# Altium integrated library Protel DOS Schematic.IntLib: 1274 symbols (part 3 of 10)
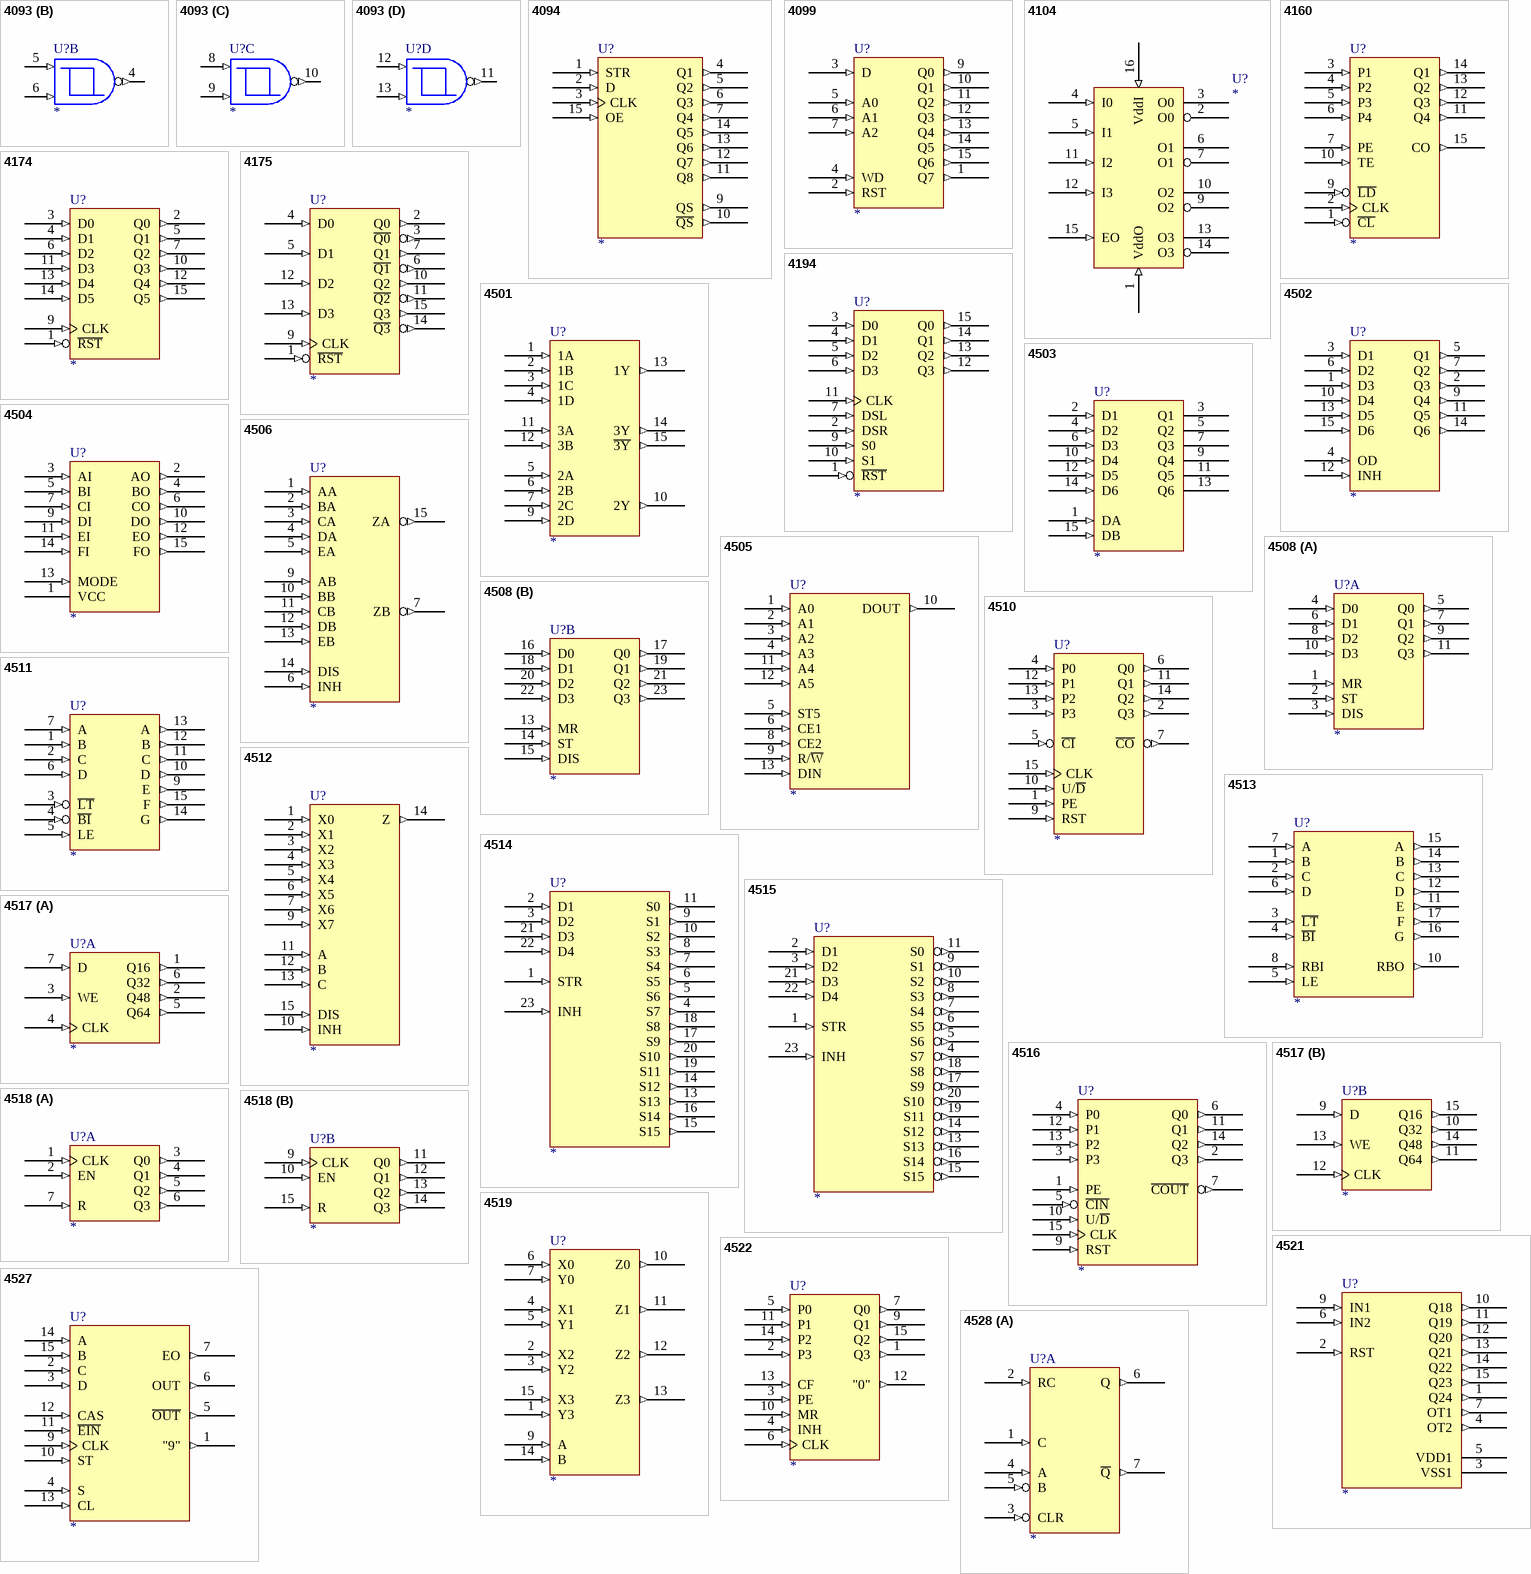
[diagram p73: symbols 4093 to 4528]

## 4511
designator U?
footprint DIP16E
footprint DIP-16
pins: 1 B (in), 2 C (in), 3 ~{LT} (in), 4 ~{BI} (in), 5 LE (in), 6 D (in), 7 A (in), 8 GND (power) hidden to GND, 9 E (out), 10 D (out), 11 C (out), 12 B (out), 13 A (out), 14 G (out), 15 F (out), 16 VCC (power) hidden to VCC
2 alternate drawings of the same symbol

## 4512
designator U?
footprint DIP-16
pins: 1 X0 (in), 2 X1 (in), 3 X2 (in), 4 X3 (in), 5 X4 (in), 6 X5 (in), 7 X6 (in), 8 GND (power) hidden to GND, 9 X7 (in), 10 INH (in), 11 A (in), 12 B (in), 13 C (in), 14 Z (out), 15 DIS (in), 16 VCC (power) hidden to VCC
2 alternate drawings of the same symbol

## 4513
designator U?
footprint DIP-18
pins: 1 B (in), 2 C (in), 3 ~{LT} (in), 4 ~{BI} (in), 5 LE (in), 6 D (in), 7 A (in), 8 RBI (in), 9 GND (power) hidden to GND, 10 RBO (out), 11 E (out), 12 D (out), 13 C (out), 14 B (out), 15 A (out), 16 G (out), 17 F (out), 18 VCC (power) hidden to VCC
2 alternate drawings of the same symbol

## 4514
designator U?
footprint DIP-24
pins: 1 STR (in), 2 D1 (in), 3 D2 (in), 4 S7 (out), 5 S6 (out), 6 S5 (out), 7 S4 (out), 8 S3 (out), 9 S1 (out), 10 S2 (out), 11 S0 (out), 12 GND (power) hidden to GND, 13 S13 (out), 14 S12 (out), 15 S15 (out), 16 S14 (out), 17 S9 (out), 18 S8 (out), 19 S11 (out), 20 S10 (out), 21 D3 (in), 22 D4 (in), 23 INH (in), 24 VCC (power) hidden to VCC
2 alternate drawings of the same symbol

## 4515
designator U?
footprint DIP-24
pins: 1 STR (in), 2 D1 (in), 3 D2 (in), 4 S7 (out), 5 S6 (out), 6 S5 (out), 7 S4 (out), 8 S3 (out), 9 S1 (out), 10 S2 (out), 11 S0 (out), 12 GND (power) hidden to GND, 13 S13 (out), 14 S12 (out), 15 S15 (out), 16 S14 (out), 17 S9 (out), 18 S8 (out), 19 S11 (out), 20 S10 (out), 21 D3 (in), 22 D4 (in), 23 INH (in), 24 VCC (power) hidden to VCC
2 alternate drawings of the same symbol

## 4516
designator U?
footprint DIP16E
pins: 1 PE (in), 2 Q3 (out), 3 P3 (in), 4 P0 (in), 5 ~{CIN} (in), 6 Q0 (out), 7 ~{COUT} (out), 8 GND (power) hidden to GND, 9 RST (in), 10 U/~{D} (in), 11 Q1 (out), 12 P1 (in), 13 P2 (in), 14 Q2 (out), 15 CLK (in), 16 VCC (power) hidden to VCC
2 alternate drawings of the same symbol

## 4517
designator U?
footprint DIP-16
part A pins: 1 Q16 (out), 2 Q48 (out), 3 WE (in), 4 CLK (in), 5 Q64 (out), 6 Q32 (out), 7 D (in), 8 GND (power) hidden to GND, 16 VCC (power) hidden to VCC
part B pins: 8 GND (power) hidden to GND, 9 D (in), 10 Q32 (out), 11 Q64 (out), 12 CLK (in), 13 WE (in), 14 Q48 (out), 15 Q16 (out), 16 VCC (power) hidden to VCC
2 alternate drawings of the same symbol

## 4518
designator U?
footprint DIP-16
part A pins: 1 CLK (in), 2 EN (in), 3 Q0 (out), 4 Q1 (out), 5 Q2 (out), 6 Q3 (out), 7 R (in), 8 GND (power) hidden to GND, 16 VCC (power) hidden to VCC
part B pins: 8 GND (power) hidden to GND, 9 CLK (in), 10 EN (in), 11 Q0 (out), 12 Q1 (out), 13 Q2 (out), 14 Q3 (out), 15 R (in), 16 VCC (power) hidden to VCC
2 alternate drawings of the same symbol

## 4519
designator U?
footprint DIP-16
pins: 1 Y3 (in), 2 X2 (in), 3 Y2 (in), 4 X1 (in), 5 Y1 (in), 6 X0 (in), 7 Y0 (in), 8 GND (power) hidden to GND, 9 A (in), 10 Z0 (out), 11 Z1 (out), 12 Z2 (out), 13 Z3 (out), 14 B (in), 15 X3 (in), 16 VCC (power) hidden to VCC
2 alternate drawings of the same symbol

## 4521
designator U?
footprint DIP-16
pins: 1 Q24 (out), 2 RST (in), 3 VSS1 (power), 4 OT2 (out), 5 VDD1 (power), 6 IN2 (in), 7 OT1 (out), 8 GND (power) hidden to GND, 9 IN1 (in), 10 Q18 (out), 11 Q19 (out), 12 Q20 (out), 13 Q21 (out), 14 Q22 (out), 15 Q23 (out), 16 VCC (power) hidden to VCC
2 alternate drawings of the same symbol

## 4522
designator U?
footprint DIP-16
pins: 1 Q3 (out), 2 P3 (in), 3 PE (in), 4 INH (in), 5 P0 (in), 6 CLK (in), 7 Q0 (out), 8 GND (power) hidden to GND, 9 Q1 (out), 10 MR (in), 11 P1 (in), 12 "0" (out), 13 CF (in), 14 P2 (in), 15 Q2 (out), 16 VCC (power) hidden to VCC
2 alternate drawings of the same symbol

## 4527
designator U?
footprint DIP-16
pins: 1 "9" (out), 2 C (in), 3 D (in), 4 S (in), 5 ~{OUT} (out), 6 OUT (out), 7 EO (out), 8 GND (power) hidden to GND, 9 CLK (in), 10 ST (in), 11 ~{EIN} (in), 12 CAS (in), 13 CL (in), 14 A (in), 15 B (in), 16 VCC (power) hidden to VCC
2 alternate drawings of the same symbol

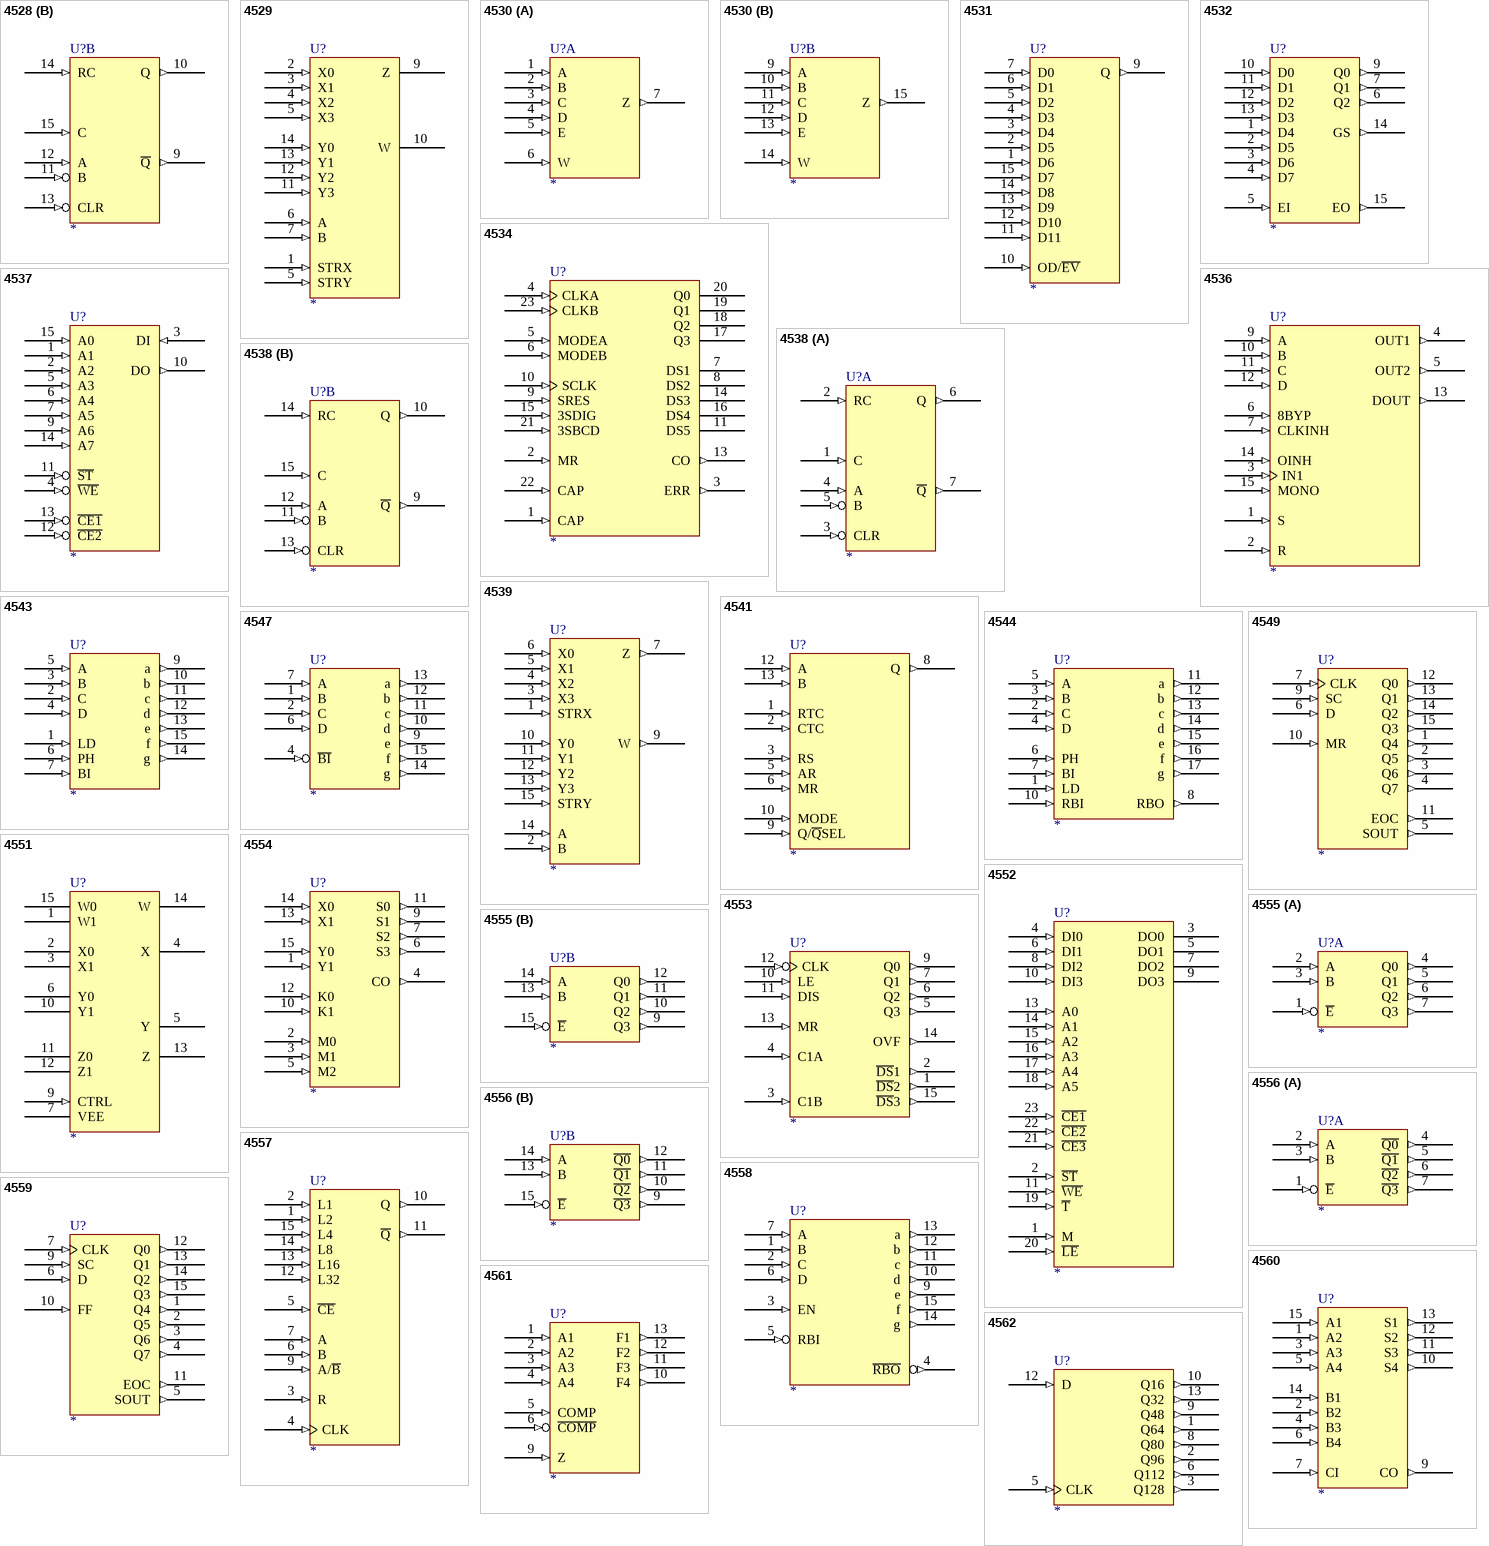
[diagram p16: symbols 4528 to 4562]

## 4528
designator U?
footprint DIP-16
part A pins: 1 C (in), 2 RC (in), 3 CLR (in), 4 A (in), 5 B (in), 6 Q (out), 7 ~{Q} (out), 8 GND (power) hidden to GND, 16 VCC (power) hidden to VCC
part B pins: 8 GND (power) hidden to GND, 9 ~{Q} (out), 10 Q (out), 11 B (in), 12 A (in), 13 CLR (in), 14 RC (in), 15 C (in), 16 VCC (power) hidden to VCC
2 alternate drawings of the same symbol

## 4529
designator U?
footprint DIP-16
pins: 1 STRX (in), 2 X0 (in), 3 X1 (in), 4 X2 (in), 5 X3 (in), 5 STRY (in), 6 A (in), 7 B (in), 8 GND (power) hidden to GND, 9 Z, 10 W, 11 Y3 (in), 12 Y2 (in), 13 Y1 (in), 14 Y0 (in), 16 VCC (power) hidden to VCC
2 alternate drawings of the same symbol

## 4530
designator U?
footprint DIP-16
part A pins: 1 A (in), 2 B (in), 3 C (in), 4 D (in), 5 E (in), 6 W (in), 7 Z (out), 8 GND (power) hidden to GND, 16 VCC (power) hidden to VCC
part B pins: 8 GND (power) hidden to GND, 9 A (in), 10 B (in), 11 C (in), 12 D (in), 13 E (in), 14 W (in), 15 Z (out), 16 VCC (power) hidden to VCC
2 alternate drawings of the same symbol

## 4531
designator U?
footprint DIP-16
pins: 1 D6 (in), 2 D5 (in), 3 D4 (in), 4 D3 (in), 5 D2 (in), 6 D1 (in), 7 D0 (in), 8 GND (power) hidden to GND, 9 Q (out), 10 OD/~{EV} (in), 11 D11 (in), 12 D10 (in), 13 D9 (in), 14 D8 (in), 15 D7 (in), 16 VCC (power) hidden to VCC
2 alternate drawings of the same symbol

## 4532
designator U?
footprint DIP-16
pins: 1 D4 (in), 2 D5 (in), 3 D6 (in), 4 D7 (in), 5 EI (in), 6 Q2 (out), 7 Q1 (out), 8 GND (power) hidden to GND, 9 Q0 (out), 10 D0 (in), 11 D1 (in), 12 D2 (in), 13 D3 (in), 14 GS (out), 15 EO (out), 16 VCC (power) hidden to VCC
2 alternate drawings of the same symbol

## 4534
designator U?
footprint DIP-24
pins: 1 CAP (in), 2 MR (in), 3 ERR (out), 4 CLKA (in), 5 MODEA (in), 6 MODEB (in), 7 DS1 (hiz), 8 DS2 (hiz), 9 SRES (in), 10 SCLK (in), 11 DS5 (hiz), 12 GND (power) hidden to GND, 13 CO (out), 14 DS3 (hiz), 15 3SDIG (in), 16 DS4 (hiz), 17 Q3 (hiz), 18 Q2 (hiz), 19 Q1 (hiz), 20 Q0 (hiz), 21 3SBCD (in), 22 CAP (in), 23 CLKB (in), 24 VCC (power) hidden to VCC
2 alternate drawings of the same symbol

## 4536
designator U?
footprint DIP-16
pins: 1 S (in), 2 R (in), 3 IN1 (in), 4 OUT1 (out), 5 OUT2 (out), 6 8BYP (in), 7 CLKINH (in), 8 GND (power) hidden to GND, 9 A (in), 10 B (in), 11 C (in), 12 D (in), 13 DOUT (out), 14 OINH (in), 15 MONO (in), 16 VCC (power) hidden to VCC
2 alternate drawings of the same symbol

## 4537
designator U?
footprint DIP-16
pins: 1 A1 (in), 2 A2 (in), 3 DI (in), 4 ~{WE} (in), 5 A3 (in), 6 A4 (in), 7 A5 (in), 8 GND (power) hidden to GND, 9 A6 (in), 10 DO (out), 11 ~{ST} (in), 12 ~{CE2} (in), 13 ~{CE1} (in), 14 A7 (in), 15 A0 (in), 16 VCC (power) hidden to VCC
2 alternate drawings of the same symbol

## 4538
designator U?
footprint DIP-16
part A pins: 1 C (in), 2 RC (in), 3 CLR (in), 4 A (in), 5 B (in), 6 Q (out), 7 ~{Q} (out), 8 GND (power) hidden to GND, 16 VCC (power) hidden to VCC
part B pins: 8 GND (power) hidden to GND, 9 ~{Q} (out), 10 Q (out), 11 B (in), 12 A (in), 13 CLR (in), 14 RC (in), 15 C (in), 16 VCC (power) hidden to VCC
2 alternate drawings of the same symbol

## 4539
designator U?
footprint DIP-16
pins: 1 STRX (in), 2 B (in), 3 X3 (in), 4 X2 (in), 5 X1 (in), 6 X0 (in), 7 Z (out), 8 GND (power) hidden to GND, 9 W (out), 10 Y0 (in), 11 Y1 (in), 12 Y2 (in), 13 Y3 (in), 14 A (in), 15 STRY (in), 16 VCC (power) hidden to VCC
2 alternate drawings of the same symbol

## 4541
designator U?
footprint DIP-14
pins: 1 RTC (in), 2 CTC (in), 3 RS (in), 5 AR (in), 6 MR (in), 7 GND (power) hidden to GND, 8 Q (out), 9 Q/~{Q}SEL (in), 10 MODE (in), 12 A (in), 13 B (in), 14 VCC (power) hidden to VCC
2 alternate drawings of the same symbol

## 4543
designator U?
footprint DIP-16
pins: 1 LD (in), 2 C (in), 3 B (in), 4 D (in), 5 A (in), 6 PH (in), 7 BI (in), 8 GND (power) hidden to GND, 9 a (out), 10 b (out), 11 c (out), 12 d (out), 13 e (out), 14 g (out), 15 f (out), 16 VCC (power) hidden to VCC
2 alternate drawings of the same symbol

## 4544
designator U?
footprint DIP-18
pins: 1 LD (in), 2 C (in), 3 B (in), 4 D (in), 5 A (in), 6 PH (in), 7 BI (in), 8 RBO (out), 9 GND (power) hidden to GND, 10 RBI (in), 11 a (out), 12 b (out), 13 c (out), 14 d (out), 15 e (out), 16 f (out), 17 g (out), 18 VCC (power) hidden to VCC
2 alternate drawings of the same symbol

## 4547
designator U?
footprint DIP-16
pins: 1 B (in), 2 C (in), 4 ~{BI} (in), 6 D (in), 7 A (in), 8 GND (power) hidden to GND, 9 e (out), 10 d (out), 11 c (out), 12 b (out), 13 a (out), 14 g (out), 15 f (out), 16 VCC (power) hidden to VCC
2 alternate drawings of the same symbol

## 4549
designator U?
footprint DIP-16
pins: 1 Q4 (out), 2 Q5 (out), 3 Q6 (out), 4 Q7 (out), 5 SOUT (out), 6 D (in), 7 CLK (in), 8 GND (power) hidden to GND, 9 SC (in), 10 MR (in), 11 EOC (out), 12 Q0 (out), 13 Q1 (out), 14 Q2 (out), 15 Q3 (out), 16 VCC (power) hidden to VCC
2 alternate drawings of the same symbol

## 4551
designator U?
footprint DIP-16
pins: 1 W1, 2 X0, 3 X1, 4 X, 5 Y, 6 Y0, 7 VEE, 8 GND (power) hidden to GND, 9 CTRL (in), 10 Y1, 11 Z0, 12 Z1, 13 Z, 14 W, 15 W0, 16 VCC (power) hidden to VCC
2 alternate drawings of the same symbol

## 4552
designator U?
footprint DIP-24
pins: 1 M (in), 2 ~{ST} (in), 3 DO0 (hiz), 4 DI0 (in), 5 DO1 (hiz), 6 DI1 (in), 7 DO2 (hiz), 8 DI2 (in), 9 DO3 (hiz), 10 DI3 (in), 11 ~{WE} (in), 12 GND (power) hidden to GND, 13 A0 (in), 14 A1 (in), 15 A2 (in), 16 A3 (in), 17 A4 (in), 18 A5 (in), 19 ~{T} (in), 20 ~{LE} (in), 21 ~{CE3} (in), 22 ~{CE2} (in), 23 ~{CE1} (in), 24 VCC (power) hidden to VCC
2 alternate drawings of the same symbol

## 4553
designator U?
footprint DIP16E
footprint DIP-16
pins: 1 ~{DS}2 (out), 2 ~{DS}1 (out), 3 C1B (in), 4 C1A (in), 5 Q3 (out), 6 Q2 (out), 7 Q1 (out), 8 GND (power) hidden to GND, 9 Q0 (out), 10 LE (in), 11 DIS (in), 12 CLK (in), 13 MR (in), 14 OVF (out), 15 ~{DS}3 (out), 16 VCC (power) hidden to VCC
2 alternate drawings of the same symbol

## 4554
designator U?
footprint DIP-16
pins: 1 Y1 (in), 2 M0 (in), 3 M1 (in), 4 CO (out), 5 M2 (in), 6 S3 (out), 7 S2 (out), 8 GND (power) hidden to GND, 9 S1 (out), 10 K1 (in), 11 S0 (out), 12 K0 (in), 13 X1 (in), 14 X0 (in), 15 Y0 (in), 16 VCC (power) hidden to VCC
2 alternate drawings of the same symbol

## 4555
designator U?
footprint DIP-16
part A pins: 1 ~{E} (in), 2 A (in), 3 B (in), 4 Q0 (out), 5 Q1 (out), 6 Q2 (out), 7 Q3 (out), 8 GND (power) hidden to GND, 16 VCC (power) hidden to VCC
part B pins: 8 GND (power) hidden to GND, 9 Q3 (out), 10 Q2 (out), 11 Q1 (out), 12 Q0 (out), 13 B (in), 14 A (in), 15 ~{E} (in), 16 VCC (power) hidden to VCC
2 alternate drawings of the same symbol

## 4556
designator U?
footprint DIP-16
part A pins: 1 ~{E} (in), 2 A (in), 3 B (in), 4 ~{Q0} (out), 5 ~{Q1} (out), 6 ~{Q2} (out), 7 ~{Q3} (out), 8 GND (power) hidden to GND, 16 VCC (power) hidden to VCC
part B pins: 8 GND (power) hidden to GND, 9 ~{Q3} (out), 10 ~{Q2} (out), 11 ~{Q1} (out), 12 ~{Q0} (out), 13 B (in), 14 A (in), 15 ~{E} (in), 16 VCC (power) hidden to VCC
2 alternate drawings of the same symbol

## 4557
designator U?
footprint DIP-16
pins: 1 L2 (in), 2 L1 (in), 3 R (in), 4 CLK (in), 5 ~{CE} (in), 6 B (in), 7 A (in), 8 GND (power) hidden to GND, 9 A/~{B} (in), 10 Q (out), 11 ~{Q} (out), 12 L32 (in), 13 L16 (in), 14 L8 (in), 15 L4 (in), 16 VCC (power) hidden to VCC
2 alternate drawings of the same symbol

## 4558
designator U?
footprint DIP-16
pins: 1 B (in), 2 C (in), 3 EN (in), 4 ~{RBO} (out), 5 RBI (in), 6 D (in), 7 A (in), 8 GND (power) hidden to GND, 9 e (out), 10 d (out), 11 c (out), 12 b (out), 13 a (out), 14 g (out), 15 f (out), 16 VCC (power) hidden to VCC
2 alternate drawings of the same symbol

## 4559
designator U?
footprint DIP-16
pins: 1 Q4 (out), 2 Q5 (out), 3 Q6 (out), 4 Q7 (out), 5 SOUT (out), 6 D (in), 7 CLK (in), 8 GND (power) hidden to GND, 9 SC (in), 10 FF (in), 11 EOC (out), 12 Q0 (out), 13 Q1 (out), 14 Q2 (out), 15 Q3 (out), 16 VCC (power) hidden to VCC
2 alternate drawings of the same symbol

## 4560
designator U?
footprint DIP-16
pins: 1 A2 (in), 2 B2 (in), 3 A3 (in), 4 B3 (in), 5 A4 (in), 6 B4 (in), 7 CI (in), 8 GND (power) hidden to GND, 9 CO (out), 10 S4 (out), 11 S3 (out), 12 S2 (out), 13 S1 (out), 14 B1 (in), 15 A1 (in), 16 VCC (power) hidden to VCC
2 alternate drawings of the same symbol

## 4561
designator U?
footprint DIP-14
pins: 1 A1 (in), 2 A2 (in), 3 A3 (in), 4 A4 (in), 5 COMP (in), 6 ~{COMP} (in), 7 GND (power) hidden to GND, 9 Z (in), 10 F4 (out), 11 F3 (out), 12 F2 (out), 13 F1 (out), 14 VCC (power) hidden to VCC
2 alternate drawings of the same symbol

## 4562
designator U?
footprint DIP-14
pins: 1 Q64 (out), 2 Q96 (out), 3 Q128 (out), 5 CLK (in), 6 Q112 (out), 7 GND (power) hidden to GND, 8 Q80 (out), 9 Q48 (out), 10 Q16 (out), 12 D (in), 13 Q32 (out), 14 VCC (power) hidden to VCC
2 alternate drawings of the same symbol

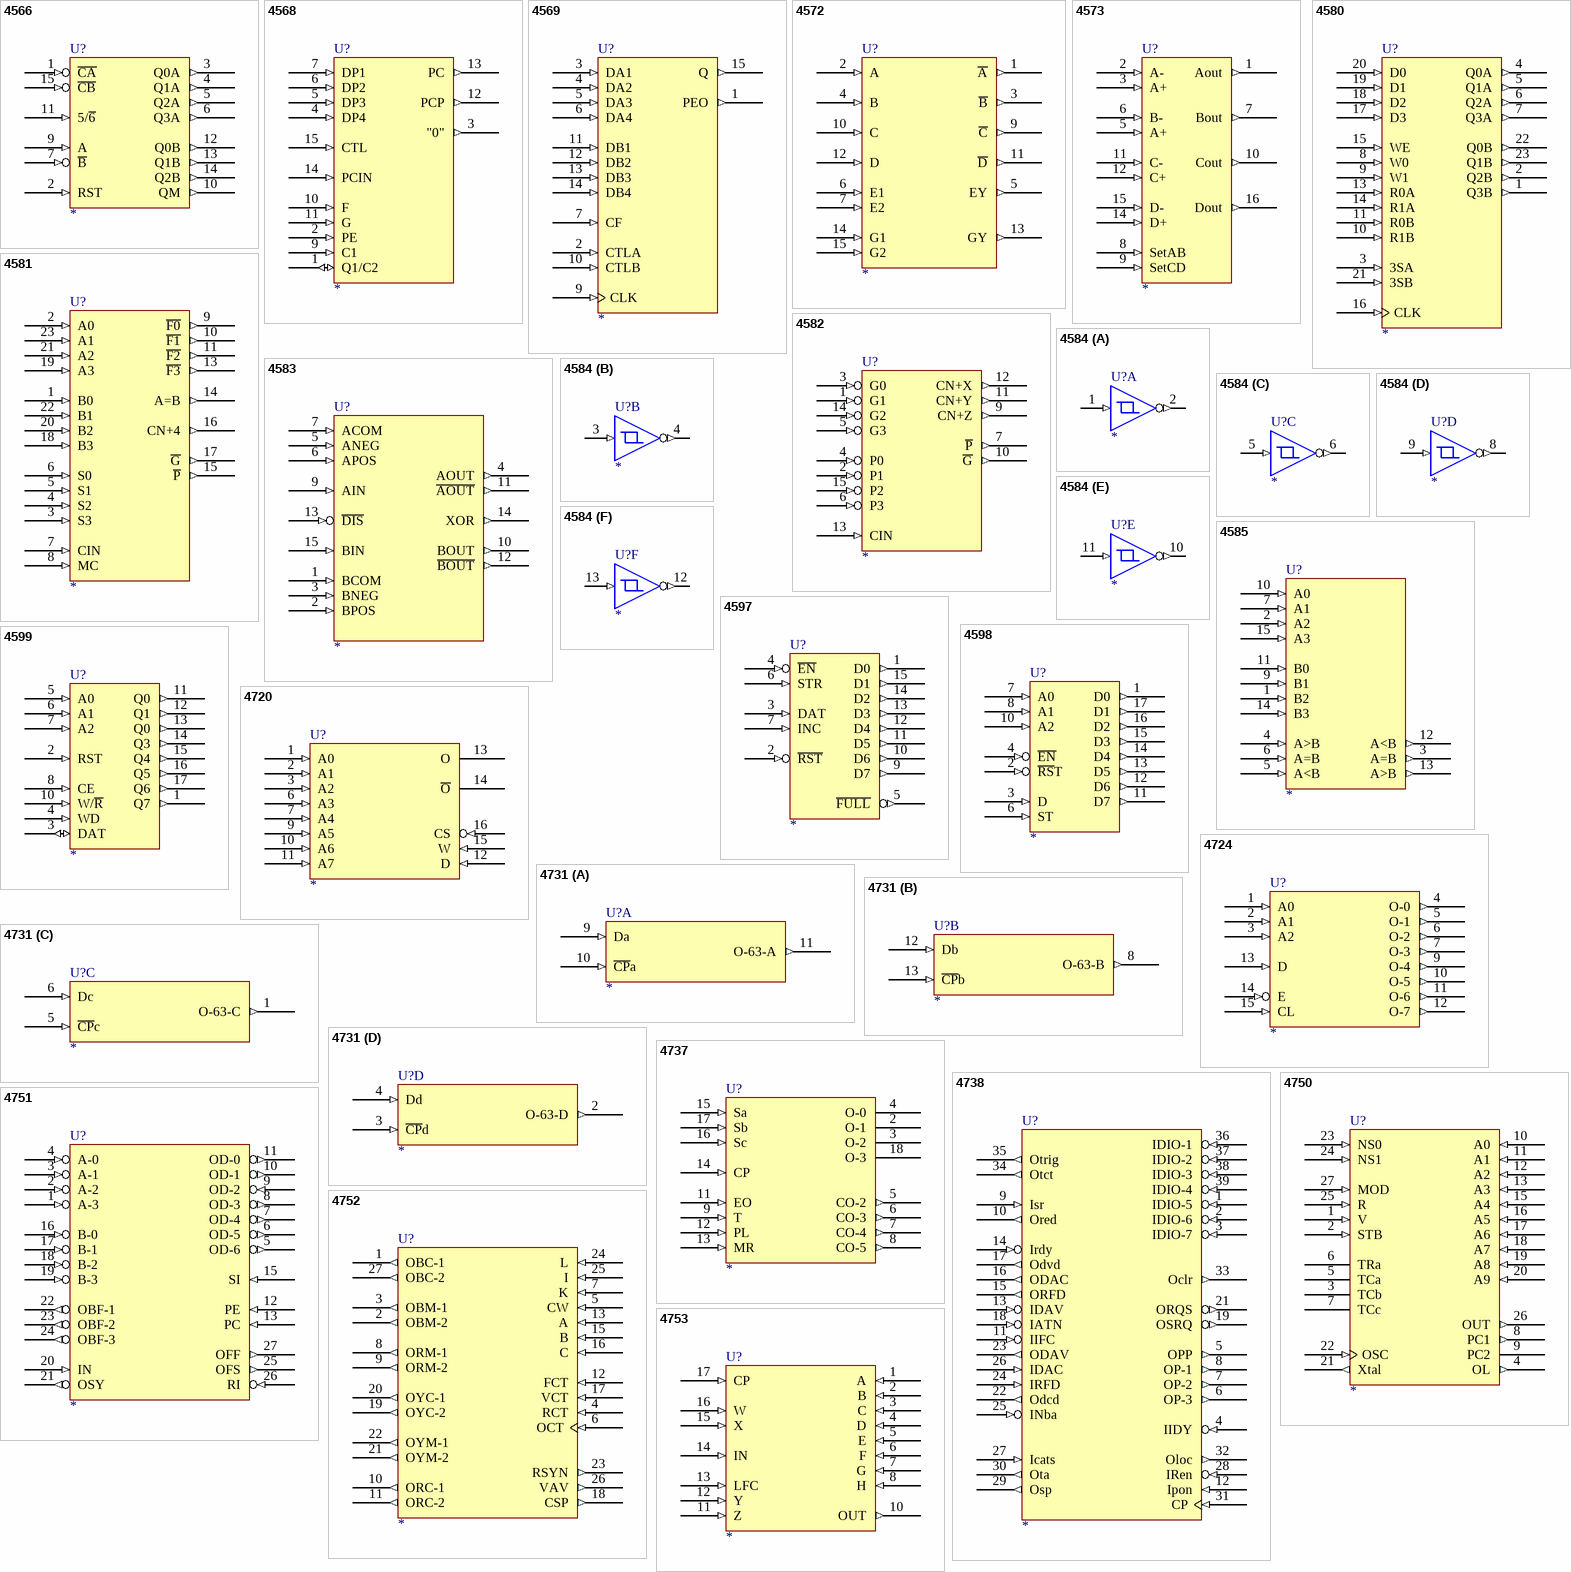
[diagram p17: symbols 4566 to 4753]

## 4566
designator U?
footprint DIP-16
pins: 1 ~{CA} (in), 2 RST (in), 3 Q0A (out), 4 Q1A (out), 5 Q2A (out), 6 Q3A (out), 7 ~{B} (in), 8 GND (power) hidden to GND, 9 A (in), 10 QM (out), 11 5/~{6} (in), 12 Q0B (out), 13 Q1B (out), 14 Q2B (out), 15 ~{CB} (in), 16 VCC (power) hidden to VCC
2 alternate drawings of the same symbol

## 4568
designator U?
footprint DIP-16
pins: 1 Q1/C2 (io), 2 PE (in), 3 "0" (out), 4 DP4 (in), 5 DP3 (in), 6 DP2 (in), 7 DP1 (in), 8 GND (power) hidden to GND, 9 C1 (in), 10 F (in), 11 G (in), 12 PCP (out), 13 PC (out), 14 PCIN (in), 15 CTL (in), 16 VCC (power) hidden to VCC
2 alternate drawings of the same symbol

## 4569
designator U?
footprint DIP-16
pins: 1 PEO (out), 2 CTLA (in), 3 DA1 (in), 4 DA2 (in), 5 DA3 (in), 6 DA4 (in), 7 CF (in), 8 GND (power) hidden to GND, 9 CLK (in), 10 CTLB (in), 11 DB1 (in), 12 DB2 (in), 13 DB3 (in), 14 DB4 (in), 15 Q (out), 16 VCC (power) hidden to VCC
2 alternate drawings of the same symbol

## 4572
designator U?
footprint DIP-16
pins: 1 ~{A} (out), 2 A (in), 3 ~{B} (out), 4 B (in), 5 EY (out), 6 E1 (in), 7 E2 (in), 8 GND (power) hidden to GND, 9 ~{C} (out), 10 C (in), 11 ~{D} (out), 12 D (in), 13 GY (out), 14 G1 (in), 15 G2 (in), 16 VCC (power) hidden to VCC
2 alternate drawings of the same symbol

## 4573
designator U?
footprint DIP-16
pins: 1 Aout (out), 2 A- (in), 3 A+ (in), 4 VCC (power) hidden to VCC, 5 A+ (in), 6 B- (in), 7 Bout (out), 8 SetAB (in), 9 SetCD (in), 10 Cout (out), 11 C- (in), 12 C+ (in), 13 GND (power) hidden to GND, 14 D+ (in), 15 D- (in), 16 Dout (out)
2 alternate drawings of the same symbol

## 4580
designator U?
footprint DIP-24
pins: 1 Q3B (out), 2 Q2B (out), 3 3SA (in), 4 Q0A (out), 5 Q1A (out), 6 Q2A (out), 7 Q3A (out), 8 W0 (in), 9 W1 (in), 10 R1B (in), 11 R0B (in), 12 GND (power) hidden to GND, 13 R0A (in), 14 R1A (in), 15 WE (in), 16 CLK (in), 17 D3 (in), 18 D2 (in), 19 D1 (in), 20 D0 (in), 21 3SB (in), 22 Q0B (out), 23 Q1B (out), 24 VCC (power) hidden to VCC
2 alternate drawings of the same symbol

## 4581
designator U?
footprint DIP-24
pins: 1 B0 (in), 2 A0 (in), 3 S3 (in), 4 S2 (in), 5 S1 (in), 6 S0 (in), 7 CIN (in), 8 MC (in), 9 ~{F0} (out), 10 ~{F1} (out), 11 ~{F2} (out), 12 GND (power) hidden to GND, 13 ~{F3} (out), 14 A=B (out), 15 ~{P} (out), 16 CN+4 (out), 17 ~{G} (out), 18 B3 (in), 19 A3 (in), 20 B2 (in), 21 A2 (in), 22 B1 (in), 23 A1 (in), 24 VCC (power) hidden to VCC
2 alternate drawings of the same symbol

## 4582
designator U?
footprint DIP-16
pins: 1 G1 (in), 2 P1 (in), 3 G0 (in), 4 P0 (in), 5 G3 (in), 6 P3 (in), 7 ~{P} (out), 8 GND (power) hidden to GND, 9 CN+Z (out), 10 ~{G} (out), 11 CN+Y (out), 12 CN+X (out), 13 CIN (in), 14 G2 (in), 15 P2 (in), 16 VCC (power) hidden to VCC
2 alternate drawings of the same symbol

## 4583
designator U?
footprint DIP-16
pins: 1 BCOM (in), 2 BPOS (in), 3 BNEG (in), 4 AOUT (out), 5 ANEG (in), 6 APOS (in), 7 ACOM (in), 8 GND (power) hidden to GND, 9 AIN (in), 10 BOUT (out), 11 ~{AOUT} (out), 12 ~{BOUT} (out), 13 ~{DIS} (in), 14 XOR (out), 15 BIN (in), 16 VCC (power) hidden to VCC
2 alternate drawings of the same symbol

## 4584
designator U?
footprint DIP14E
part A pins: 1 (in), 2 (out), 7 GND (power) hidden to GND, 14 VCC (power) hidden to VCC
part B pins: 3 (in), 4 (out), 7 GND (power) hidden to GND, 14 VCC (power) hidden to VCC
part C pins: 5 (in), 6 (out), 7 GND (power) hidden to GND, 14 VCC (power) hidden to VCC
part D pins: 7 GND (power) hidden to GND, 8 (out), 9 (in), 14 VCC (power) hidden to VCC
part E pins: 7 GND (power) hidden to GND, 10 (out), 11 (in), 14 VCC (power) hidden to VCC
part F pins: 7 GND (power) hidden to GND, 12 (out), 13 (in), 14 VCC (power) hidden to VCC
2 alternate drawings of the same symbol

## 4585
designator U?
footprint DIP-16
pins: 1 B2 (in), 2 A2 (in), 3 A=B (out), 4 A>B (in), 5 A<B (in), 6 A=B (in), 7 A1 (in), 8 GND (power) hidden to GND, 9 B1 (in), 10 A0 (in), 11 B0 (in), 12 A<B (out), 13 A>B (out), 14 B3 (in), 15 A3 (in), 16 VCC (power) hidden to VCC
2 alternate drawings of the same symbol

## 4597
designator U?
footprint DIP-16
pins: 1 D0 (out), 2 ~{RST} (in), 3 DAT (in), 4 ~{EN} (in), 5 ~{FULL} (out), 6 STR (in), 7 INC (in), 8 GND (power) hidden to GND, 9 D7 (out), 10 D6 (out), 11 D5 (out), 12 D4 (out), 13 D3 (out), 14 D2 (out), 15 D1 (out), 16 VCC (power) hidden to VCC
2 alternate drawings of the same symbol

## 4598
designator U?
footprint DIP-16
pins: 1 D0 (out), 2 ~{RS}T (in), 3 D (in), 4 ~{EN} (in), 6 ST (in), 7 A0 (in), 8 GND (power) hidden to GND, 8 A1 (in), 10 A2 (in), 11 D7 (out), 12 D6 (out), 13 D5 (out), 14 D4 (out), 15 D3 (out), 16 VCC (power) hidden to VCC, 16 D2 (out), 17 D1 (out)
2 alternate drawings of the same symbol

## 4599
designator U?
footprint DIP-18
pins: 1 Q7 (out), 2 RST (in), 3 DAT (io), 4 WD (in), 5 A0 (in), 6 A1 (in), 7 A2 (in), 8 CE (in), 9 GND (power) hidden to GND, 10 W/~{R} (in), 11 Q0 (out), 12 Q1 (out), 13 Q0 (out), 14 Q3 (out), 15 Q4 (out), 16 Q5 (out), 17 Q6 (out), 18 VCC (power) hidden to VCC
2 alternate drawings of the same symbol

## 4720
designator U?
footprint DIP-16
pins: 1 A0 (in), 2 A1 (in), 3 A2 (in), 5 VCC (power) hidden to VCC, 6 A3 (in), 7 A4 (in), 8 GND (power) hidden to GND, 9 A5 (in), 10 A6 (in), 11 A7 (in), 12 D (in), 13 O (hiz), 14 ~{O} (hiz), 15 W (in), 16 CS (in)
2 alternate drawings of the same symbol

## 4724
designator U?
footprint DIP-16
pins: 1 A0 (in), 2 A1 (in), 3 A2 (in), 4 O-0 (out), 5 O-1 (out), 6 O-2 (out), 7 O-3 (out), 8 GND (power) hidden to GND, 9 O-4 (out), 10 O-5 (out), 11 O-6 (out), 12 O-7 (out), 13 D (in), 14 E (in), 15 CL (in), 16 VCC (power) hidden to VCC
2 alternate drawings of the same symbol

## 4731
designator U?
footprint DIP-14
part A pins: 7 GND (power) hidden to GND, 9 Da (in), 10 ~{CP}a (in), 11 O-63-A (out), 14 VCC (power) hidden to VCC
part B pins: 7 GND (power) hidden to GND, 8 O-63-B (out), 12 Db (in), 13 ~{CP}b (in), 14 VCC (power) hidden to VCC
part C pins: 1 O-63-C (out), 5 ~{CP}c (in), 6 Dc (in), 7 GND (power) hidden to GND, 14 VCC (power) hidden to VCC
part D pins: 2 O-63-D (out), 3 ~{CP}d (in), 4 Dd (in), 7 GND (power) hidden to GND, 14 VCC (power) hidden to VCC
2 alternate drawings of the same symbol

## 4737
designator U?
footprint DIP-18
pins: 1 GND (power) hidden to GND, 2 O-1 (hiz), 3 O-2 (hiz), 4 O-0 (hiz), 5 CO-2 (out), 6 CO-3 (out), 7 CO-4 (out), 8 CO-5 (out), 9 T (in), 10 VCC (power) hidden to VCC, 11 EO (in), 12 PL (in), 13 MR (in), 14 CP (in), 15 Sa (in), 16 Sc (in), 17 Sb (in), 18 O-3 (hiz)
2 alternate drawings of the same symbol

## 4738
designator U?
footprint DIP-40
pins: 1 IDIO-5 (in), 2 IDIO-6 (in), 3 IDIO-7 (in), 4 IIDY (in), 5 OPP (out), 6 OP-3 (out), 7 OP-2 (out), 8 OP-1 (out), 9 Isr (in), 10 Ored (out), 11 IIFC (in), 12 Ipon (in), 13 IDAV (in), 14 Irdy (in), 15 ORFD (out), 16 ODAC (out), 17 Odvd (out), 18 IATN (in), 19 OSRQ (out), 20 GND (power) hidden to GND, 21 ORQS (out), 22 Odcd (out), 23 ODAV (out), 24 IRFD (in), 25 INba (in), 26 IDAC (in), 27 Icats (in), 28 IRen (in), 29 Osp (out), 30 Ota (out), 31 CP (in), 32 Oloc (out), 33 Oclr (out), 34 Otct (out), 35 Otrig (out), 36 IDIO-1 (in), 37 IDIO-2 (in), 38 IDIO-3 (in), 39 IDIO-4 (in), 40 VCC (power) hidden to VCC
2 alternate drawings of the same symbol

## 4750
designator U?
footprint DIP-28
pins: 1 V (in), 2 STB (in), 3 TCb, 4 OL (out), 5 TCa, 6 TRa, 7 TCc, 8 PC1 (out), 9 PC2 (hiz), 10 A0 (in), 11 A1 (in), 12 A2 (in), 13 A3 (in), 14 GND (power) hidden to GND, 15 A4 (in), 16 A5 (in), 17 A6 (in), 18 A7 (in), 19 A8 (in), 20 A9 (in), 21 Xtal (out), 22 OSC (in), 23 NS0 (in), 24 NS1 (in), 25 R (in), 26 OUT (out), 27 MOD (in), 28 VCC (power) hidden to VCC
2 alternate drawings of the same symbol

## 4751
designator U?
footprint DIP-28
pins: 1 A-3 (in), 2 A-2 (in), 3 A-1 (in), 4 A-0 (in), 5 OD-6 (out), 6 OD-5 (out), 7 OD-4 (out), 8 OD-3 (out), 9 OD-2 (in), 10 OD-1 (out), 11 OD-0 (out), 12 PE (in), 13 PC (in), 14 GND (power) hidden to GND, 15 SI (in), 16 B-0 (in), 17 B-1 (in), 18 B-2 (in), 19 B-3 (in), 20 IN (in), 21 OSY (out), 22 OBF-1 (out), 23 OBF-2 (out), 24 OBF-3 (out), 25 OFS (out), 26 RI (in), 27 OFF (out), 28 VCC (power) hidden to VCC
2 alternate drawings of the same symbol

## 4752
designator U?
footprint DIP-28
pins: 1 OBC-1 (out), 2 OBM-2 (out), 3 OBM-1 (out), 4 RCT (in), 5 CW (in), 6 OCT (in), 7 K (in), 8 ORM-1 (out), 9 ORM-2 (out), 10 ORC-1 (out), 11 ORC-2 (out), 12 FCT (in), 13 A (in), 14 GND (power) hidden to GND, 15 B (in), 16 C (in), 17 VCT (in), 18 CSP (out), 19 OYC-2 (out), 20 OYC-1 (out), 21 OYM-2 (out), 22 OYM-1 (out), 23 RSYN (out), 24 L (in), 25 I (in), 26 VAV (out), 27 OBC-2 (out), 28 VCC (power) hidden to VCC
2 alternate drawings of the same symbol

## 4753
designator U?
footprint DIP-18
pins: 1 A (in), 2 B (in), 3 C (in), 4 D (in), 5 E (in), 6 F (in), 7 G (in), 8 H (in), 9 GND (power) hidden to GND, 10 OUT (out), 11 Z (in), 12 Y (in), 13 LFC (in), 14 IN (in), 15 X (in), 16 W (in), 17 CP (in), 18 VCC (power) hidden to VCC
2 alternate drawings of the same symbol

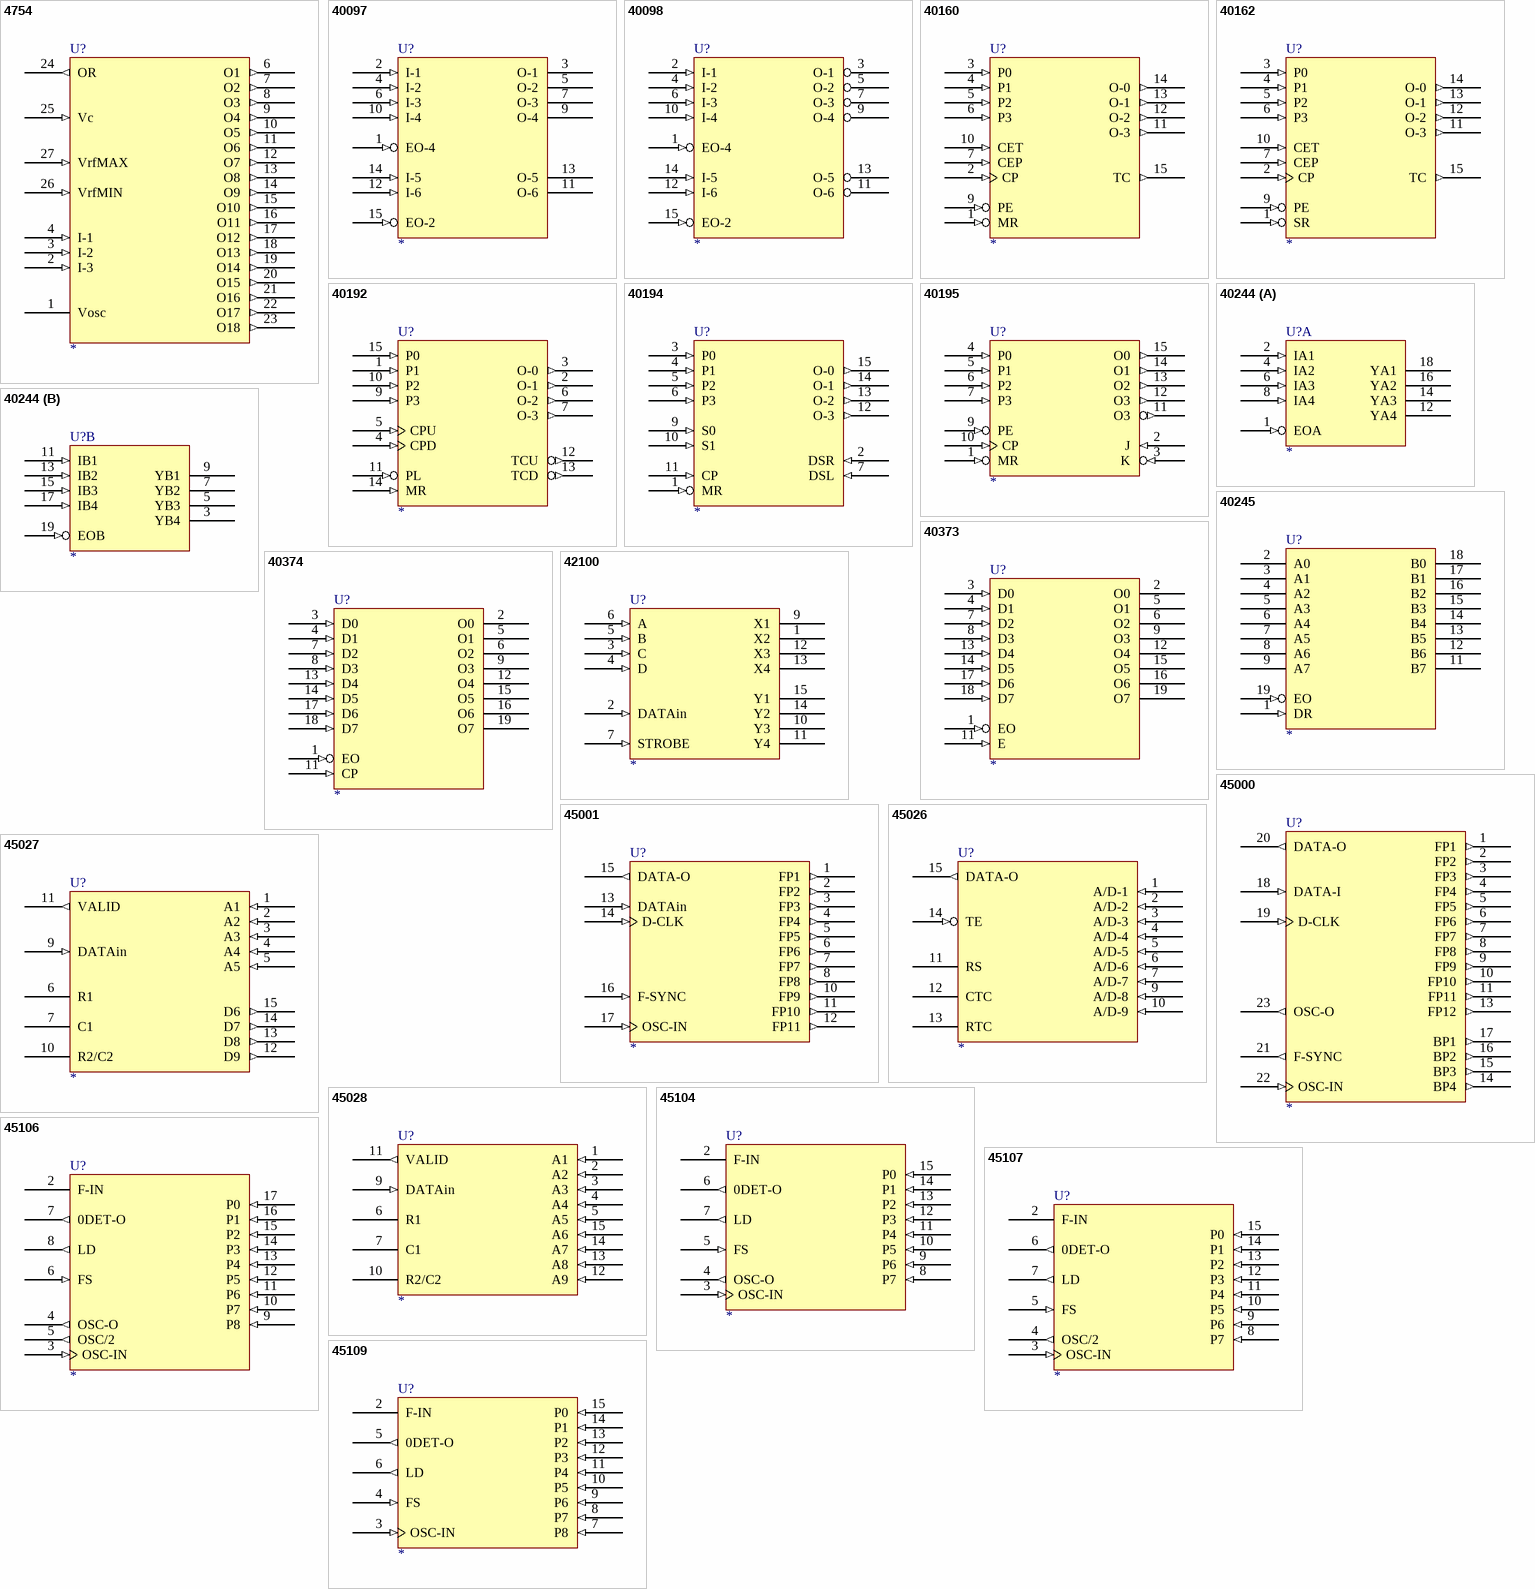
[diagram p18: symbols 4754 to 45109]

## 4754
designator U?
footprint DIP-28
pins: 1 Vosc, 2 I-3 (in), 3 I-2 (in), 4 I-1 (in), 5 GND (power) hidden to GND, 6 O1 (out), 7 O2 (out), 8 O3 (out), 9 O4 (out), 10 O5 (out), 11 O6 (out), 12 O7 (out), 13 O8 (out), 14 O9 (out), 15 O10 (out), 16 O11 (out), 17 O12 (out), 18 O13 (out), 19 O14 (out), 20 O15 (out), 21 O16 (out), 22 O17 (out), 23 O18 (out), 24 OR (out), 25 Vc (in), 26 VrfMIN (in), 27 VrfMAX (in), 28 VCC (power) hidden to VCC
2 alternate drawings of the same symbol

## 40097
designator U?
footprint DIP-16
pins: 1 EO-4 (in), 2 I-1 (in), 3 O-1 (hiz), 4 I-2 (in), 5 O-2 (hiz), 6 I-3 (in), 7 O-3 (hiz), 8 GND (power) hidden to GND, 9 O-4 (hiz), 10 I-4 (in), 11 O-6 (hiz), 12 I-6 (in), 13 O-5 (hiz), 14 I-5 (in), 15 EO-2 (in), 16 VCC (power) hidden to VCC
2 alternate drawings of the same symbol

## 40098
designator U?
footprint DIP-16
pins: 1 EO-4 (in), 2 I-1 (in), 3 O-1 (hiz), 4 I-2 (in), 5 O-2 (hiz), 6 I-3 (in), 7 O-3 (hiz), 8 GND (power) hidden to GND, 9 O-4 (hiz), 10 I-4 (in), 11 O-6 (hiz), 12 I-6 (in), 13 O-5 (hiz), 14 I-5 (in), 15 EO-2 (in), 16 VCC (power) hidden to VCC
2 alternate drawings of the same symbol

## 40160
designator U?
footprint DIP-16
pins: 1 MR (in), 2 CP (in), 3 P0 (in), 4 P1 (in), 5 P2 (in), 6 P3 (in), 7 CEP (in), 8 GND (power) hidden to GND, 9 PE (in), 10 CET (in), 11 O-3 (out), 12 O-2 (out), 13 O-1 (out), 14 O-0 (out), 15 TC (out), 16 VCC (power) hidden to VCC
2 alternate drawings of the same symbol

## 40162
designator U?
footprint DIP-16
pins: 1 SR (in), 2 CP (in), 3 P0 (in), 4 P1 (in), 5 P2 (in), 6 P3 (in), 7 CEP (in), 8 GND (power) hidden to GND, 9 PE (in), 10 CET (in), 11 O-3 (out), 12 O-2 (out), 13 O-1 (out), 14 O-0 (out), 15 TC (out), 16 VCC (power) hidden to VCC
2 alternate drawings of the same symbol

## 40192
designator U?
footprint DIP-16
pins: 1 P1 (in), 2 O-1 (out), 3 O-0 (out), 4 CPD (in), 5 CPU (in), 6 O-2 (out), 7 O-3 (out), 8 GND (power) hidden to GND, 9 P3 (in), 10 P2 (in), 11 PL (in), 12 TCU (out), 13 TCD (out), 14 MR (in), 15 P0 (in), 16 VCC (power) hidden to VCC
2 alternate drawings of the same symbol

## 40194
designator U?
footprint DIP-16
pins: 1 MR (in), 2 DSR (in), 3 P0 (in), 4 P1 (in), 5 P2 (in), 6 P3 (in), 7 DSL (in), 8 GND (power) hidden to GND, 9 S0 (in), 10 S1 (in), 11 CP (in), 12 O-3 (out), 13 O-2 (out), 14 O-1 (out), 15 O-0 (out), 16 VCC (power) hidden to VCC
2 alternate drawings of the same symbol

## 40195
designator U?
footprint DIP-16
pins: 1 MR (in), 2 J (in), 3 K (in), 4 P0 (in), 5 P1 (in), 6 P2 (in), 7 P3 (in), 8 GND (power) hidden to GND, 9 PE (in), 10 CP (in), 11 O3 (out), 12 O3 (out), 13 O2 (out), 14 O1 (out), 15 O0 (out), 16 VCC (power) hidden to VCC
2 alternate drawings of the same symbol

## 40244
designator U?
footprint DIP-20
part A pins: 1 EOA (in), 2 IA1 (in), 4 IA2 (in), 6 IA3 (in), 8 IA4 (in), 10 GND (power) hidden to GND, 12 YA4 (hiz), 14 YA3 (hiz), 16 YA2 (hiz), 18 YA1 (hiz), 20 VCC (power) hidden to VCC
part B pins: 3 YB4 (hiz), 5 YB3 (hiz), 7 YB2 (hiz), 9 YB1 (hiz), 10 GND (power) hidden to GND, 11 IB1 (in), 13 IB2 (in), 15 IB3 (in), 17 IB4 (in), 19 EOB (in), 20 VCC (power) hidden to VCC
2 alternate drawings of the same symbol

## 40245
designator U?
footprint DIP-20
pins: 1 DR (in), 2 A0 (hiz), 3 A1 (hiz), 4 A2 (hiz), 5 A3 (hiz), 6 A4 (hiz), 7 A5 (hiz), 8 A6 (hiz), 9 A7 (hiz), 10 GND (power) hidden to GND, 11 B7 (hiz), 12 B6 (hiz), 13 B5 (hiz), 14 B4 (hiz), 15 B3 (hiz), 16 B2 (hiz), 17 B1 (hiz), 18 B0 (hiz), 19 EO (in), 20 VCC (power) hidden to VCC
2 alternate drawings of the same symbol

## 40373
designator U?
footprint DIP-20
pins: 1 EO (in), 2 O0 (hiz), 3 D0 (in), 4 D1 (in), 5 O1 (hiz), 6 O2 (hiz), 7 D2 (in), 8 D3 (in), 9 O3 (hiz), 10 GND (power) hidden to GND, 11 E (in), 12 O4 (hiz), 13 D4 (in), 14 D5 (in), 15 O5 (hiz), 16 O6 (hiz), 17 D6 (in), 18 D7 (in), 19 O7 (hiz), 20 VCC (power) hidden to VCC
2 alternate drawings of the same symbol

## 40374
designator U?
footprint DIP-20
pins: 1 EO (in), 2 O0 (hiz), 3 D0 (in), 4 D1 (in), 5 O1 (hiz), 6 O2 (hiz), 7 D2 (in), 8 D3 (in), 9 O3 (hiz), 10 GND (power) hidden to GND, 11 CP (in), 12 O4 (hiz), 13 D4 (in), 14 D5 (in), 15 O5 (hiz), 16 O6 (hiz), 17 D6 (in), 18 D7 (in), 19 O7 (hiz), 20 VCC (power) hidden to VCC
2 alternate drawings of the same symbol

## 42100
designator U?
footprint DIP-16
pins: 1 X2, 2 DATAin (in), 3 C (in), 4 D (in), 5 B (in), 6 A (in), 7 STROBE (in), 8 GND (power) hidden to GND, 9 X1, 10 Y3, 11 Y4, 12 X3, 13 X4, 14 Y2, 15 Y1, 16 VCC (power) hidden to VCC
2 alternate drawings of the same symbol

## 45000
designator U?
footprint DIP-24
pins: 1 FP1 (out), 2 FP2 (out), 3 FP3 (out), 4 FP4 (out), 5 FP5 (out), 6 FP6 (out), 7 FP7 (out), 8 FP8 (out), 9 FP9 (out), 10 FP10 (out), 11 FP11 (out), 12 GND (power) hidden to GND, 13 FP12 (out), 14 BP4 (out), 15 BP3 (out), 16 BP2 (out), 17 BP1 (out), 18 DATA-I (in), 19 D-CLK (in), 20 DATA-O (out), 21 F-SYNC (out), 22 OSC-IN (in), 23 OSC-O (out), 24 VCC (power) hidden to VCC
2 alternate drawings of the same symbol

## 45001
designator U?
footprint DIP-18
pins: 1 FP1 (out), 2 FP2 (out), 3 FP3 (out), 4 FP4 (out), 5 FP5 (out), 6 FP6 (out), 7 FP7 (out), 8 FP8 (out), 9 GND (power) hidden to GND, 10 FP9 (out), 11 FP10 (out), 12 FP11 (out), 13 DATAin (in), 14 D-CLK (in), 15 DATA-O (out), 16 F-SYNC (in), 17 OSC-IN (in), 18 VCC (power) hidden to VCC
2 alternate drawings of the same symbol

## 45026
designator U?
footprint DIP-16
pins: 1 A/D-1 (in), 2 A/D-2 (in), 3 A/D-3 (in), 4 A/D-4 (in), 5 A/D-5 (in), 6 A/D-6 (in), 7 A/D-7 (in), 8 GND (power) hidden to GND, 9 A/D-8 (in), 10 A/D-9 (in), 11 RS, 12 CTC, 13 RTC, 14 TE (in), 15 DATA-O (out), 16 VCC (power) hidden to VCC
2 alternate drawings of the same symbol

## 45027
designator U?
footprint DIP-16
pins: 1 A1 (in), 2 A2 (in), 3 A3 (in), 4 A4 (in), 5 A5 (in), 6 R1, 7 C1, 8 GND (power) hidden to GND, 9 DATAin (in), 10 R2/C2, 11 VALID (out), 12 D9 (out), 13 D8 (out), 14 D7 (out), 15 D6 (out), 16 VCC (power) hidden to VCC
2 alternate drawings of the same symbol

## 45028
designator U?
footprint DIP-16
pins: 1 A1 (in), 2 A2 (in), 3 A3 (in), 4 A4 (in), 5 A5 (in), 6 R1, 7 C1, 8 GND (power) hidden to GND, 9 DATAin (in), 10 R2/C2, 11 VALID (out), 12 A9 (in), 13 A8 (in), 14 A7 (in), 15 A6 (in), 16 VCC (power) hidden to VCC
2 alternate drawings of the same symbol

## 45104
designator U?
footprint DIP-16
pins: 1 VCC (power) hidden to VCC, 2 F-IN, 3 OSC-IN (in), 4 OSC-O (out), 5 FS (in), 6 0DET-O (out), 7 LD (out), 8 P7 (in), 9 P6 (in), 10 P5 (in), 11 P4 (in), 12 P3 (in), 13 P2 (in), 14 P1 (in), 15 P0 (in), 16 GND (power) hidden to GND
2 alternate drawings of the same symbol

## 45106
designator U?
footprint DIP-18
pins: 1 VCC (power) hidden to VCC, 2 F-IN, 3 OSC-IN (in), 4 OSC-O (out), 5 OSC/2 (out), 6 FS (in), 7 0DET-O (out), 8 LD (out), 9 P8 (in), 10 P7 (in), 11 P6 (in), 12 P5 (in), 13 P4 (in), 14 P3 (in), 15 P2 (in), 16 P1 (in), 17 P0 (in), 18 GND (power) hidden to GND
2 alternate drawings of the same symbol

## 45107
designator U?
footprint DIP-16
pins: 1 VCC (power) hidden to VCC, 2 F-IN, 3 OSC-IN (in), 4 OSC/2 (out), 5 FS (in), 6 0DET-O (out), 7 LD (out), 8 P7 (in), 9 P6 (in), 10 P5 (in), 11 P4 (in), 12 P3 (in), 13 P2 (in), 14 P1 (in), 15 P0 (in), 16 GND (power) hidden to GND
2 alternate drawings of the same symbol

## 45109
designator U?
footprint DIP-16
pins: 1 VCC (power) hidden to VCC, 2 F-IN, 3 OSC-IN (in), 4 FS (in), 5 0DET-O (out), 6 LD (out), 7 P8 (in), 8 P7 (in), 9 P6 (in), 10 P5 (in), 11 P4 (in), 12 P3 (in), 13 P2 (in), 14 P1 (in), 15 P0 (in), 16 GND (power) hidden to GND
2 alternate drawings of the same symbol

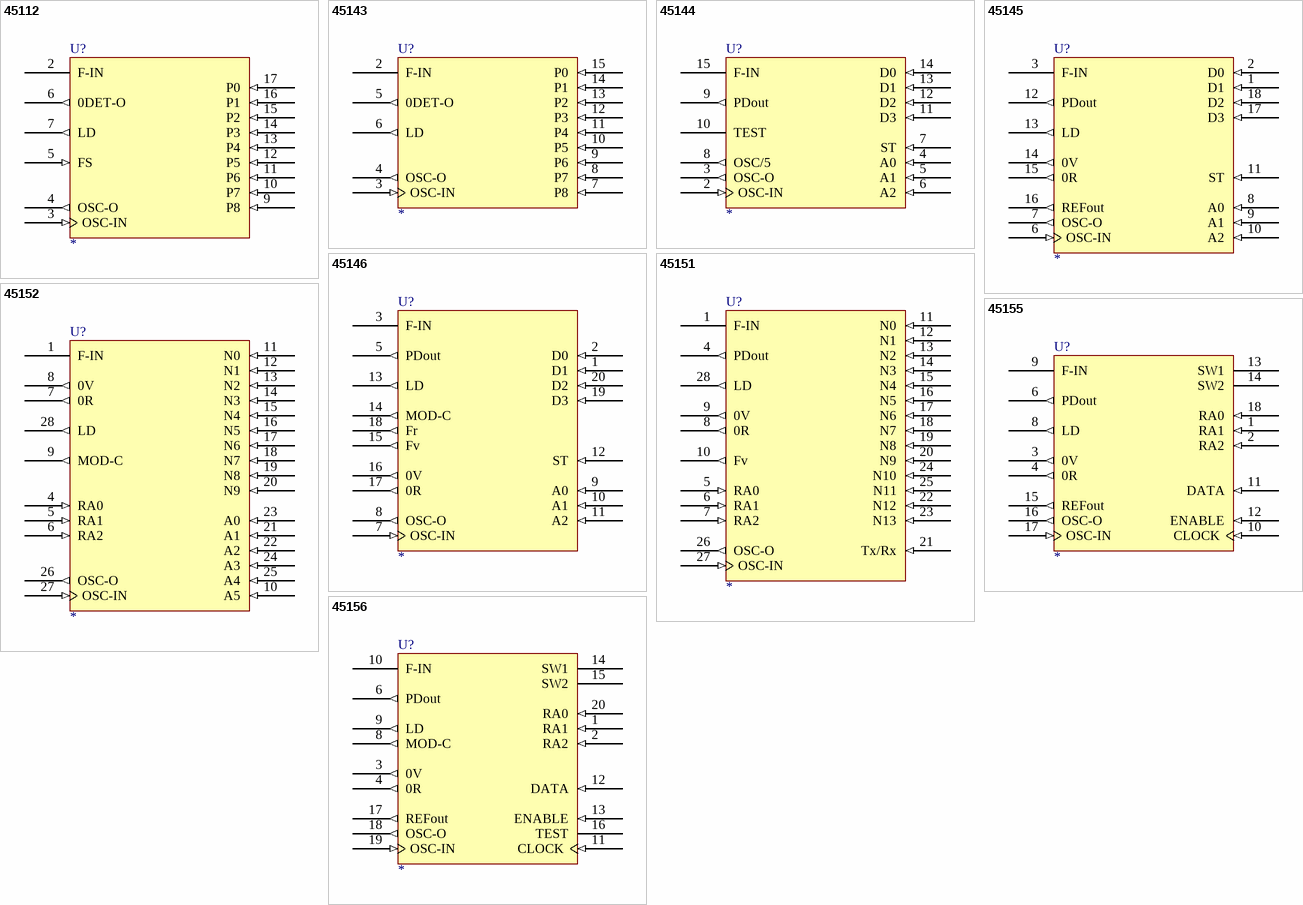
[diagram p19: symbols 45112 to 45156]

## 45112
designator U?
footprint DIP-18
pins: 1 VCC (power) hidden to VCC, 2 F-IN, 3 OSC-IN (in), 4 OSC-O (out), 5 FS (in), 6 0DET-O (out), 7 LD (out), 9 P8 (in), 10 P7 (in), 11 P6 (in), 12 P5 (in), 13 P4 (in), 14 P3 (in), 15 P2 (in), 16 P1 (in), 17 P0 (in), 18 GND (power) hidden to GND
2 alternate drawings of the same symbol

## 45143
designator U?
footprint DIP-16
pins: 1 VCC (power) hidden to VCC, 2 F-IN, 3 OSC-IN (in), 4 OSC-O (out), 5 0DET-O (out), 6 LD (out), 7 P8 (in), 8 P7 (in), 9 P6 (in), 10 P5 (in), 11 P4 (in), 12 P3 (in), 13 P2 (in), 14 P1 (in), 15 P0 (in), 16 GND (power) hidden to GND
2 alternate drawings of the same symbol

## 45144
designator U?
footprint DIP-16
pins: 1 VCC (power) hidden to VCC, 2 OSC-IN (in), 3 OSC-O (out), 4 A0 (in), 5 A1 (in), 6 A2 (in), 7 ST (in), 8 OSC/5 (out), 9 PDout (out), 10 TEST, 11 D3 (in), 12 D2 (in), 13 D1 (in), 14 D0 (in), 15 F-IN, 16 GND (power) hidden to GND
2 alternate drawings of the same symbol

## 45145
designator U?
footprint DIP-18
pins: 1 D1 (in), 2 D0 (in), 3 F-IN, 4 GND (power) hidden to GND, 5 VCC (power) hidden to VCC, 6 OSC-IN (in), 7 OSC-O (out), 8 A0 (in), 9 A1 (in), 10 A2 (in), 11 ST (in), 12 PDout (out), 13 LD (out), 14 0V (out), 15 0R (out), 16 REFout (out), 17 D3 (in), 18 D2 (in)
2 alternate drawings of the same symbol

## 45146
designator U?
footprint DIP-20
pins: 1 D1 (in), 2 D0 (in), 3 F-IN, 4 GND (power) hidden to GND, 5 PDout (out), 6 VCC (power) hidden to VCC, 7 OSC-IN (in), 8 OSC-O (out), 9 A0 (in), 10 A1 (in), 11 A2 (in), 12 ST (in), 13 LD (out), 14 MOD-C (out), 15 Fv (out), 16 0V (out), 17 0R (out), 18 Fr (out), 19 D3 (in), 20 D2 (in)
2 alternate drawings of the same symbol

## 45151
designator U?
footprint DIP-28
pins: 1 F-IN, 2 GND (power) hidden to GND, 3 VCC (power) hidden to VCC, 4 PDout (out), 5 RA0 (in), 6 RA1 (in), 7 RA2 (in), 8 0R (out), 9 0V (out), 10 Fv (out), 11 N0 (in), 12 N1 (in), 13 N2 (in), 14 N3 (in), 15 N4 (in), 16 N5 (in), 17 N6 (in), 18 N7 (in), 19 N8 (in), 20 N9 (in), 21 Tx/Rx (in), 22 N12 (in), 23 N13 (in), 24 N10 (in), 25 N11 (in), 26 OSC-O (out), 27 OSC-IN (in), 28 LD (out)
2 alternate drawings of the same symbol

## 45152
designator U?
footprint DIP-28
pins: 1 F-IN, 2 GND (power) hidden to GND, 3 VCC (power) hidden to VCC, 4 RA0 (in), 5 RA1 (in), 6 RA2 (in), 7 0R (out), 8 0V (out), 9 MOD-C (out), 10 A5 (in), 11 N0 (in), 12 N1 (in), 13 N2 (in), 14 N3 (in), 15 N4 (in), 16 N5 (in), 17 N6 (in), 18 N7 (in), 19 N8 (in), 20 N9 (in), 21 A1 (in), 22 A2 (in), 23 A0 (in), 24 A3 (in), 25 A4 (in), 26 OSC-O (out), 27 OSC-IN (in), 28 LD (out)
2 alternate drawings of the same symbol

## 45155
designator U?
footprint DIP-18
pins: 1 RA1 (in), 2 RA2 (in), 3 0V (out), 4 0R (out), 5 VCC (power) hidden to VCC, 6 PDout (out), 7 GND (power) hidden to GND, 8 LD (out), 9 F-IN, 10 CLOCK (in), 11 DATA (in), 12 ENABLE (in), 13 SW1 (oc), 14 SW2 (oc), 15 REFout (out), 16 OSC-O (out), 17 OSC-IN (in), 18 RA0 (in)
2 alternate drawings of the same symbol

## 45156
designator U?
footprint DIP-20
pins: 1 RA1 (in), 2 RA2 (in), 3 0V (out), 4 0R (out), 5 VCC (power) hidden to VCC, 6 PDout (out), 7 GND (power) hidden to GND, 8 MOD-C (out), 9 LD (out), 10 F-IN, 11 CLOCK (in), 12 DATA (in), 13 ENABLE (in), 14 SW1 (oc), 15 SW2 (oc), 16 TEST, 17 REFout (out), 18 OSC-O (out), 19 OSC-IN (in), 20 RA0 (in)
2 alternate drawings of the same symbol


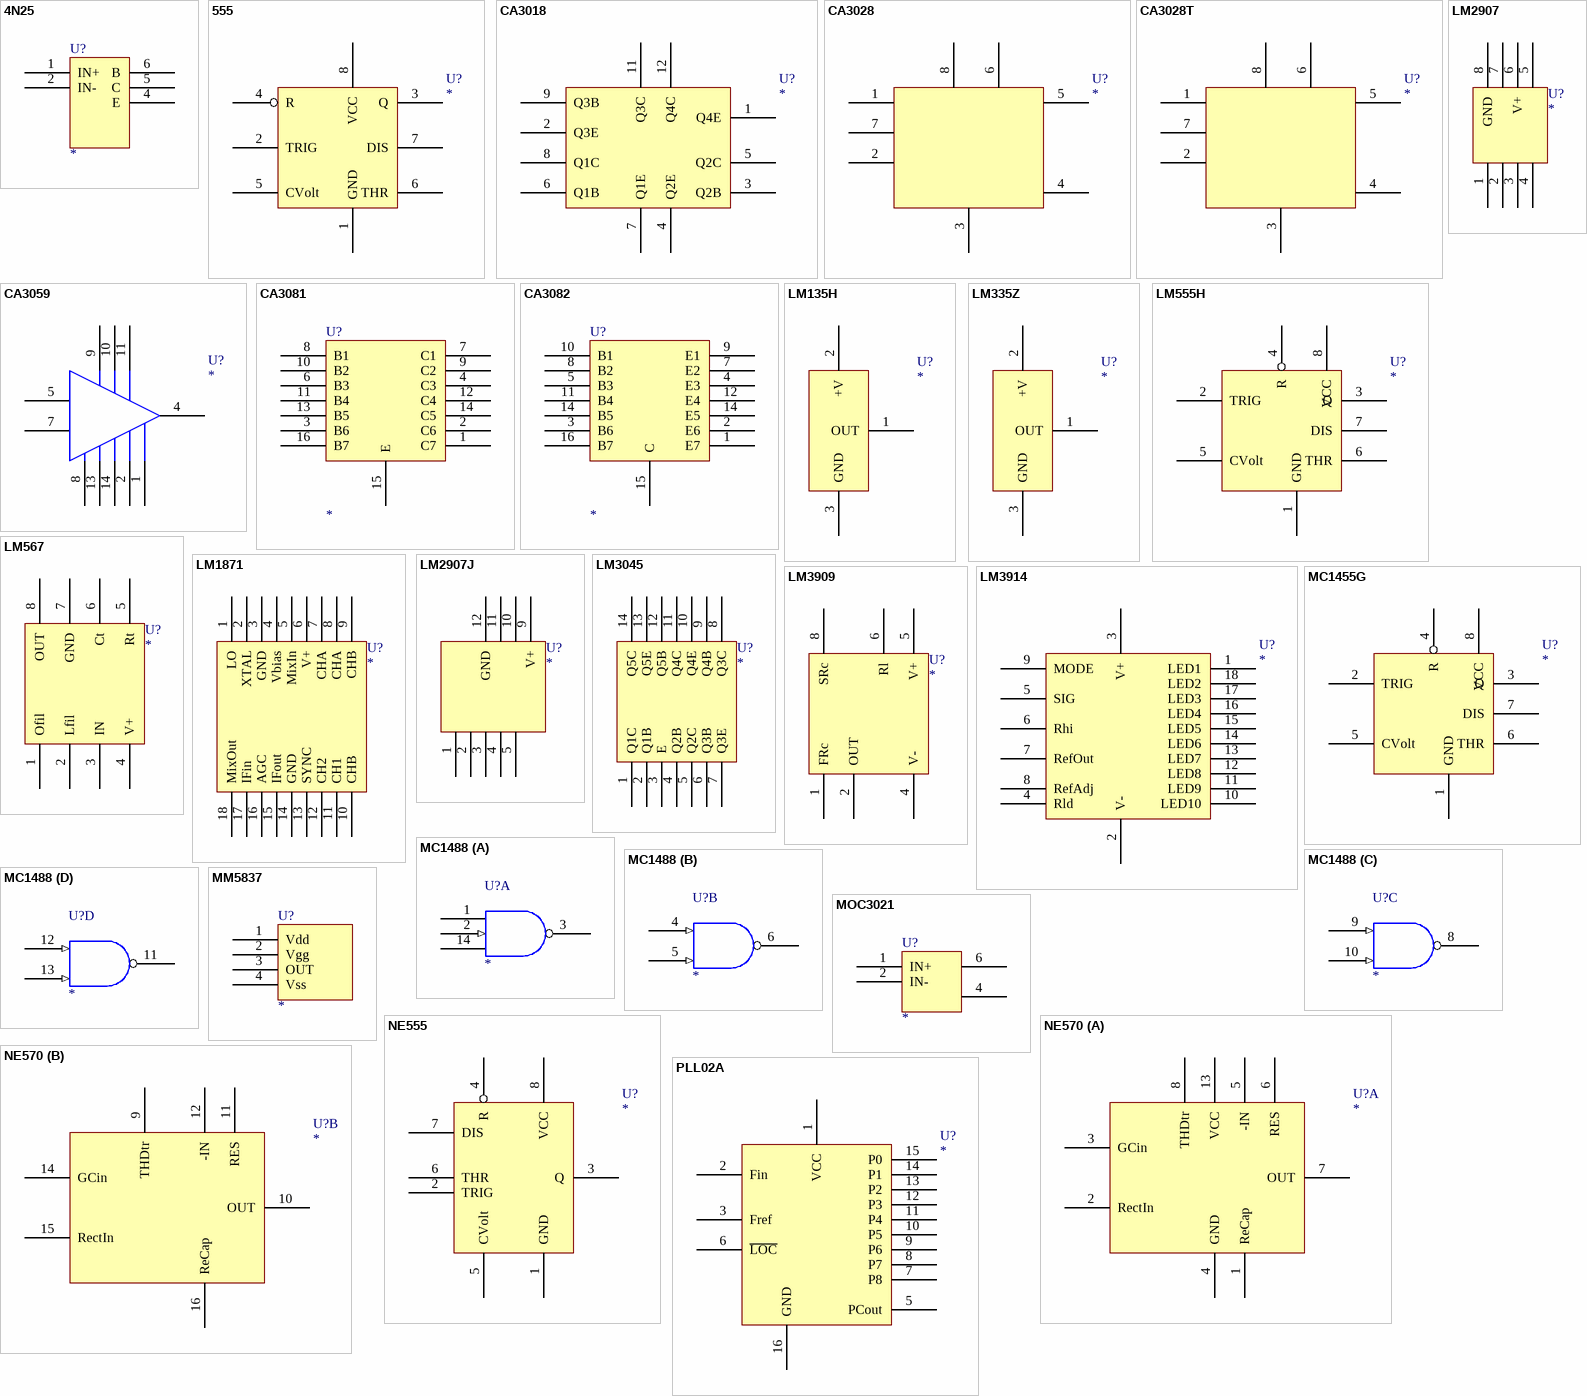
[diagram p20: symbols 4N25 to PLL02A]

## 4N25
designator U?
footprint DIP-6
pins: 1 IN+, 2 IN-, 4 E, 5 C, 6 B
2 alternate drawings of the same symbol

## 555
designator U?
footprint DIP8E
footprint DIP-8
pins: 1 GND, 2 TRIG, 3 Q, 4 R, 5 CVolt, 6 THR, 7 DIS, 8 VCC
2 alternate drawings of the same symbol

## CA3018
designator U?
footprint METAL12
pins: 1 Q4E, 2 Q3E, 3 Q2B, 4 Q2E, 5 Q2C, 6 Q1B, 7 Q1E, 8 Q1C, 9 Q3B, 11 Q3C, 12 Q4C
2 alternate drawings of the same symbol

## CA3028
designator U?
footprint DIP-8
pins: 1, 2, 3, 4, 5, 6, 7, 8
2 alternate drawings of the same symbol

## CA3028T
designator U?
footprint METAL8
pins: 1, 2, 3, 4, 5, 6, 7, 8
2 alternate drawings of the same symbol

## CA3059
designator U?
footprint DIP-14
pins: 1, 2, 4, 5, 7, 8, 9, 10, 11, 13, 14
2 alternate drawings of the same symbol

## CA3081
designator U?
footprint DIP-16
pins: 1 C7, 2 C6, 3 B6, 4 C3, 6 B3, 7 C1, 8 B1, 9 C2, 10 B2, 11 B4, 12 C4, 13 B5, 14 C5, 15 E, 16 B7
2 alternate drawings of the same symbol

## CA3082
designator U?
footprint DIP-16
pins: 1 E7, 2 E6, 3 B6, 4 E3, 5 B3, 7 E2, 8 B2, 9 E1, 10 B1, 11 B4, 12 E4, 14 B5, 14 E5, 15 C, 16 B7
2 alternate drawings of the same symbol

## LM135H
designator U?
footprint TO-46
pins: 1 OUT, 2 +V, 3 GND
2 alternate drawings of the same symbol

## LM335Z
designator U?
footprint TO-92A
pins: 1 OUT, 2 +V, 3 GND
2 alternate drawings of the same symbol

## LM555H
designator U?
footprint METAL8
pins: 1 GND, 2 TRIG, 3 Q, 4 R, 5 CVolt, 6 THR, 7 DIS, 8 VCC
2 alternate drawings of the same symbol

## LM567
designator U?
footprint DIP-8
pins: 1 Ofil, 2 Lfil, 3 IN, 4 V+, 5 Rt, 6 Ct, 7 GND, 8 OUT
2 alternate drawings of the same symbol

## LM1871
designator U?
footprint DIP-18
pins: 1 LO, 2 XTAL, 3 GND, 4 Vbias, 5 MixIn, 6 V+, 7 CHA, 8 CHA, 9 CHB, 10 CHB, 11 CH1, 12 CH2, 13 SYNC, 14 GND, 15 IFout, 16 AGC, 17 IFin, 18 MixOut
2 alternate drawings of the same symbol

## LM2907
designator U?
footprint DIP-8
pins: 1, 2, 3, 4, 5, 6 V+, 7, 8 GND
2 alternate drawings of the same symbol

## LM2907J
designator U?
footprint DIP-14
pins: 1, 2, 3, 4, 5, 9 V+, 10, 11, 12 GND
2 alternate drawings of the same symbol

## LM3045
designator U?
footprint DIP-14
pins: 1 Q1C, 2 Q1B, 3 E, 4 Q2B, 5 Q2C, 6 Q3B, 7 Q3E, 8 Q3C, 9 Q4B, 10 Q4E, 11 Q4C, 12 Q5B, 13 Q5E, 14 Q5C
2 alternate drawings of the same symbol

## LM3909
designator U?
footprint DIP-8
pins: 1 FRc, 2 OUT, 4 V-, 5 V+, 6 Rl, 8 SRc
2 alternate drawings of the same symbol

## LM3914
designator U?
footprint DIP-18
pins: 1 LED1, 2 V-, 3 V+, 4 Rld, 5 SIG, 6 Rhi, 7 RefOut, 8 RefAdj, 9 MODE, 10 LED10, 11 LED9, 12 LED8, 13 LED7, 14 LED6, 15 LED5, 16 LED4, 17 LED3, 18 LED2
2 alternate drawings of the same symbol

## MC1455G
designator U?
footprint METAL8
pins: 1 GND, 2 TRIG, 3 Q, 4 R, 5 CVolt, 6 THR, 7 DIS, 8 VCC
2 alternate drawings of the same symbol

## MC1488
designator U?
footprint DIP-14
part A pins: 1 -V (power), 2 (in), 3 (oc), 7 GND (power) hidden to GND, 14 +V (power)
part B pins: 4 (in), 5 (in), 6 (oc), 7 GND (power) hidden to GND
part C pins: 7 GND (power) hidden to GND, 8 (oc), 9 (in), 10 (in)
part D pins: 7 GND (power) hidden to GND, 11 (oc), 12 (in), 13 (in)
2 alternate drawings of the same symbol

## MM5837
designator U?
footprint DIP-8
pins: 1 Vdd, 2 Vgg, 3 OUT, 4 Vss
2 alternate drawings of the same symbol

## MOC3021
designator U?
footprint DIP6E
pins: 1 IN+, 2 IN-, 4, 6
2 alternate drawings of the same symbol

## NE555
designator U?
footprint DIP8E
pins: 1 GND, 2 TRIG, 3 Q, 4 R, 5 CVolt, 6 THR, 7 DIS, 8 VCC
2 alternate drawings of the same symbol

## NE570
designator U?
footprint DIP-16
part A pins: 1 ReCap, 2 RectIn, 3 GCin, 4 GND, 5 -IN, 6 RES, 7 OUT, 8 THDtr, 13 VCC
part B pins: 9 THDtr, 10 OUT, 11 RES, 12 -IN, 14 GCin, 15 RectIn, 16 ReCap
2 alternate drawings of the same symbol

## PLL02A
designator U?
footprint DIP-16
pins: 1 VCC, 2 Fin, 3 Fref, 5 PCout, 6 ~{LOC}, 7 P8, 8 P7, 9 P6, 10 P5, 11 P4, 12 P3, 13 P2, 14 P1, 15 P0, 16 GND
2 alternate drawings of the same symbol

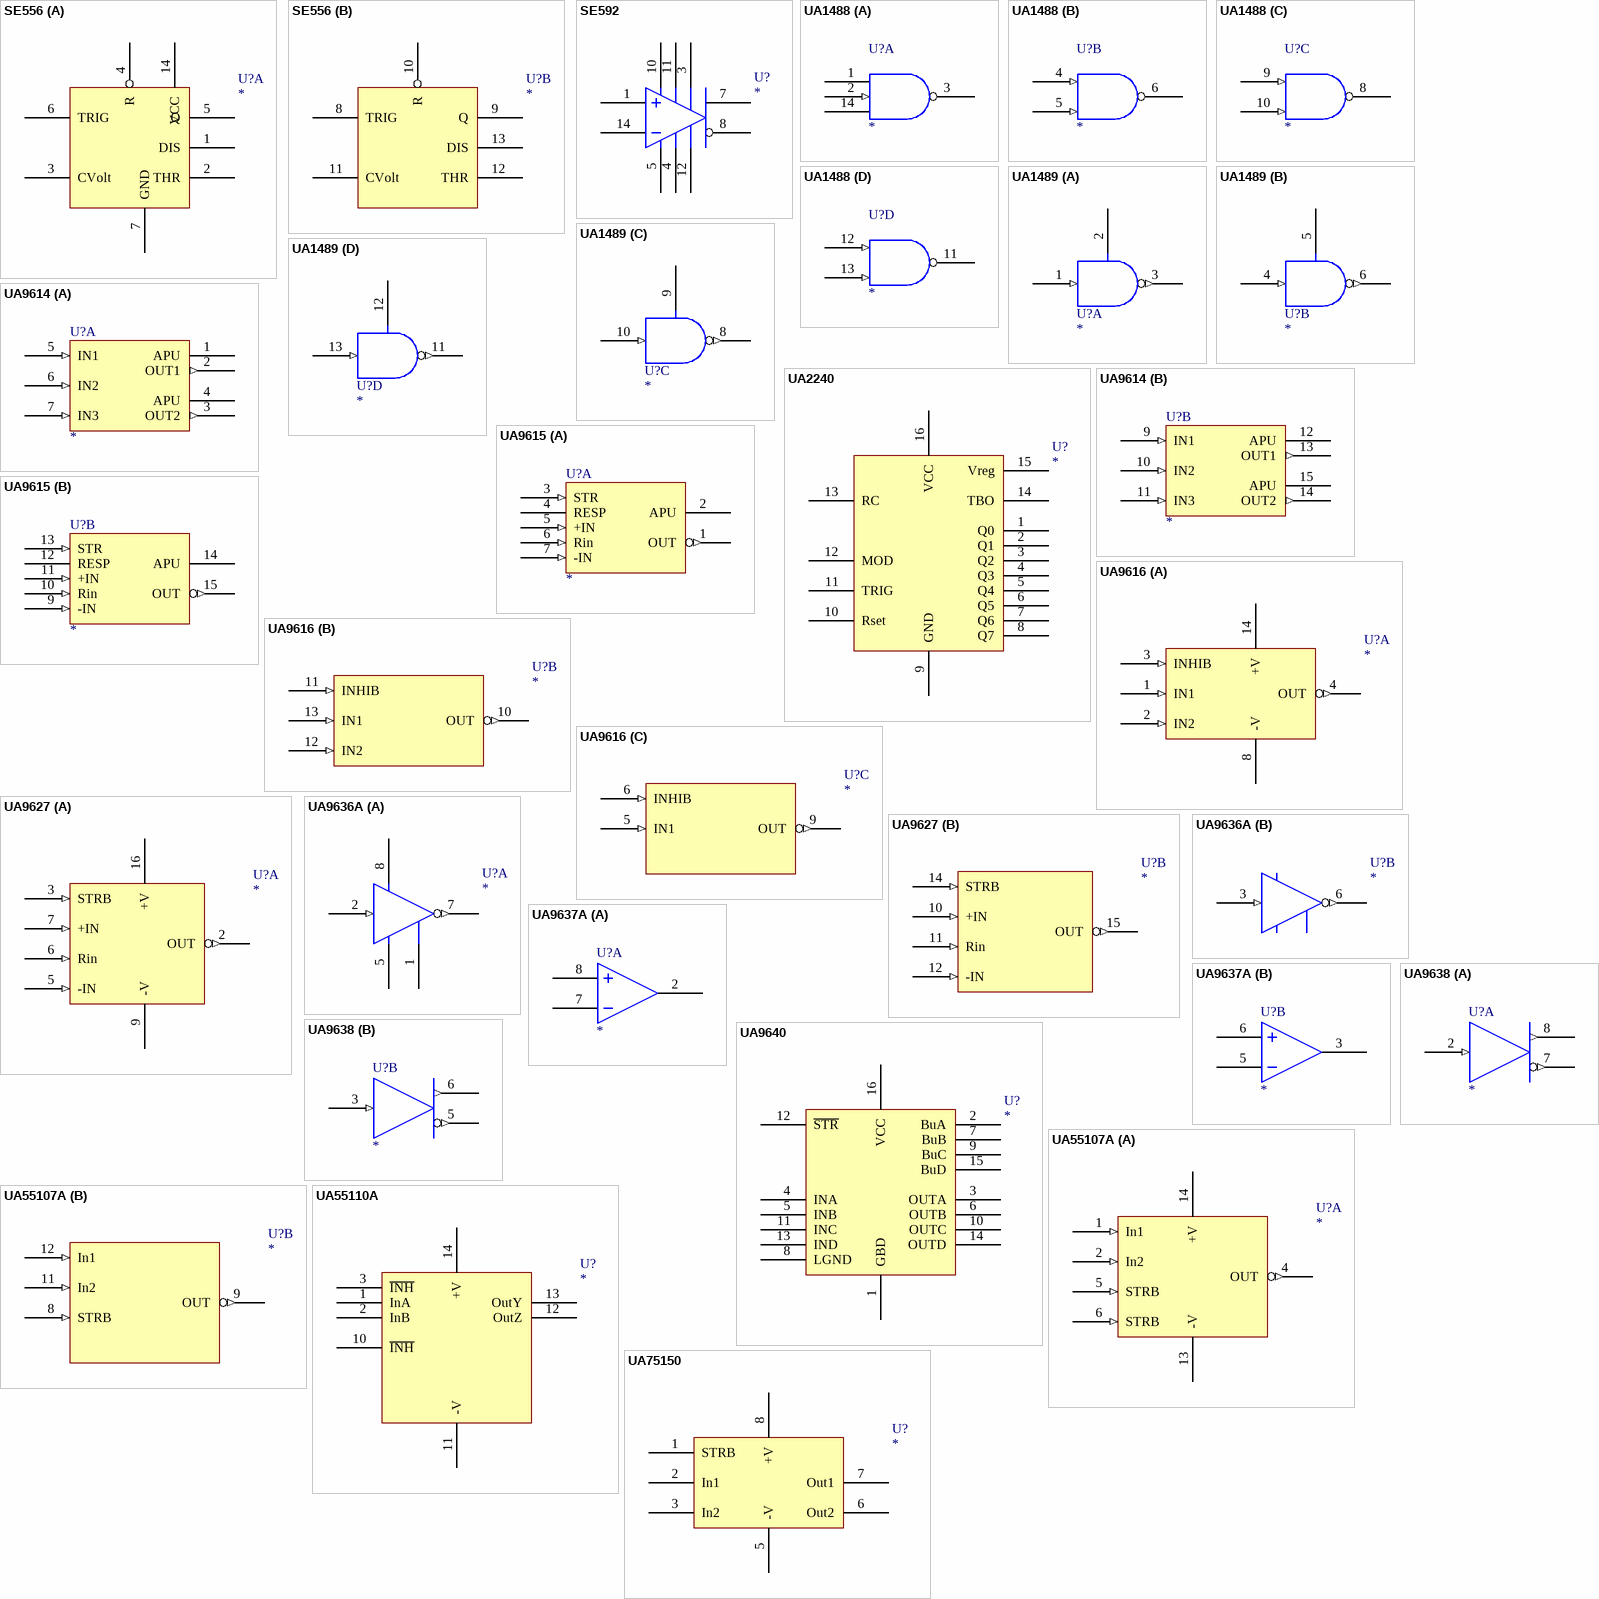
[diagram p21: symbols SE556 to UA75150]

## SE556
designator U?
footprint DIP-14
footprint DIP14E
footprint DIP14E
part A pins: 1 DIS, 2 THR, 3 CVolt, 4 R, 5 Q, 6 TRIG, 7 GND, 14 VCC
part B pins: 8 TRIG, 9 Q, 10 R, 11 CVolt, 12 THR, 13 DIS
2 alternate drawings of the same symbol

## SE592
designator U?
footprint DIP-14
pins: 1, 3, 4, 5, 7, 8, 10, 11, 12, 14
2 alternate drawings of the same symbol

## UA1488
designator U?
footprint DIP-14
part A pins: 1 -V (power), 2 (in), 3 (oc), 7 GND (power) hidden to GND, 14 +V (power)
part B pins: 4 (in), 5 (in), 6 (oc), 7 GND (power) hidden to GND
part C pins: 7 GND (power) hidden to GND, 8 (oc), 9 (in), 10 (in)
part D pins: 7 GND (power) hidden to GND, 11 (oc), 12 (in), 13 (in)
2 alternate drawings of the same symbol

## UA1489
designator U?
footprint DIP-14
part A pins: 1 (in), 2, 3 (out), 7 GND (power) hidden to GND, 14 VCC (power) hidden to VCC
part B pins: 4 (in), 5, 6 (out), 7 GND (power) hidden to GND, 14 VCC (power) hidden to VCC
part C pins: 7 GND (power) hidden to GND, 8 (out), 9, 10 (in), 14 VCC (power) hidden to VCC
part D pins: 7 GND (power) hidden to GND, 11 (out), 12, 13 (in), 14 VCC (power) hidden to VCC
2 alternate drawings of the same symbol

## UA2240
designator U?
footprint DIP-16
pins: 1 Q0, 2 Q1, 3 Q2, 4 Q3, 5 Q4, 6 Q5, 7 Q6, 8 Q7, 9 GND, 10 Rset, 11 TRIG, 12 MOD, 13 RC, 14 TBO, 15 Vreg, 16 VCC
2 alternate drawings of the same symbol

## UA9614
designator U?
footprint DIP-16
part A pins: 1 APU, 2 OUT1 (out), 3 OUT2 (out), 4 APU, 5 IN1 (in), 6 IN2 (in), 7 IN3 (in), 8 GND (power) hidden to GND, 16 VCC (power) hidden to VCC
part B pins: 8 GND (power) hidden to GND, 9 IN1 (in), 10 IN2 (in), 11 IN3 (in), 12 APU, 13 OUT1 (out), 14 OUT2 (out), 15 APU, 16 VCC (power) hidden to VCC
2 alternate drawings of the same symbol

## UA9615
designator U?
footprint DIP-16
part A pins: 1 OUT (out), 2 APU, 3 STR (in), 4 RESP, 5 +IN (in), 6 Rin (in), 7 -IN (in), 8 GND (power) hidden to GND, 16 VCC (power) hidden to VCC
part B pins: 8 GND (power) hidden to GND, 9 -IN (in), 10 Rin (in), 11 +IN (in), 12 RESP, 13 STR (in), 14 APU, 15 OUT (out), 16 VCC (power) hidden to VCC
2 alternate drawings of the same symbol

## UA9616
designator U?
footprint DIP-14
part A pins: 1 IN1 (in), 2 IN2 (in), 3 INHIB (in), 4 OUT (out), 7 GND (power) hidden to GND, 8 -V, 14 +V
part B pins: 7 GND (power) hidden to GND, 10 OUT (out), 11 INHIB (in), 12 IN2 (in), 13 IN1 (in)
part C pins: 5 IN1 (in), 6 INHIB (in), 7 GND (power) hidden to GND, 9 OUT (out)
2 alternate drawings of the same symbol

## UA9627
designator U?
footprint DIP-16
part A pins: 2 OUT (out), 3 STRB (in), 5 -IN (in), 6 Rin (in), 7 +IN (in), 8 GND (power) hidden to GND, 9 -V, 16 +V
part B pins: 8 GND (power) hidden to GND, 10 +IN (in), 11 Rin (in), 12 -IN (in), 14 STRB (in), 15 OUT (out)
2 alternate drawings of the same symbol

## UA9636A
designator U?
footprint DIP-8
part A pins: 1, 2 (in), 4 GND (power) hidden to GND, 5, 7 (out), 8
part B pins: 3 (in), 4 GND (power) hidden to GND, 6 (out)
2 alternate drawings of the same symbol

## UA9637A
designator U?
footprint DIP-8
part A pins: 1 VCC (power) hidden to VCC, 2, 4 GND (power) hidden to GND, 7, 8
part B pins: 1 VCC (power) hidden to VCC, 3, 4 GND (power) hidden to GND, 5, 6
2 alternate drawings of the same symbol

## UA9638
designator U?
footprint DIP-8
part A pins: 1 VCC (power) hidden to VCC, 2 (in), 4 GND (power) hidden to GND, 7 (out), 8 (out)
part B pins: 1 VCC (power) hidden to VCC, 3 (in), 4 GND (power) hidden to GND, 5 (out), 6 (out)
2 alternate drawings of the same symbol

## UA9640
designator U?
footprint DIP-16
pins: 1 GBD, 2 BuA, 3 OUTA, 4 INA, 5 INB, 6 OUTB, 7 BuB, 8 LGND, 9 BuC, 10 OUTC, 11 INC, 12 ~{STR}, 13 IND, 14 OUTD, 15 BuD, 16 VCC
2 alternate drawings of the same symbol

## UA55107A
designator U?
footprint DIP-14
part A pins: 1 In1 (in), 2 In2 (in), 4 OUT (out), 5 STRB (in), 6 STRB (in), 7 GND (power) hidden to GND, 13 -V, 14 +V
part B pins: 7 GND (power) hidden to GND, 8 STRB (in), 9 OUT (out), 11 In2 (in), 12 In1 (in)
2 alternate drawings of the same symbol

## UA55110A
designator U?
footprint DIP-14
pins: 1 InA, 2 InB, 3 ~{INH}, 7 GND (power) hidden to GND, 10 ~{INH}, 11 -V, 12 OutZ, 13 OutY, 14 +V
2 alternate drawings of the same symbol

## UA75150
designator U?
footprint DIP-8
pins: 1 STRB, 2 In1, 3 In2, 4 GND (power) hidden to GND, 5 -V, 6 Out2, 7 Out1, 8 +V
2 alternate drawings of the same symbol

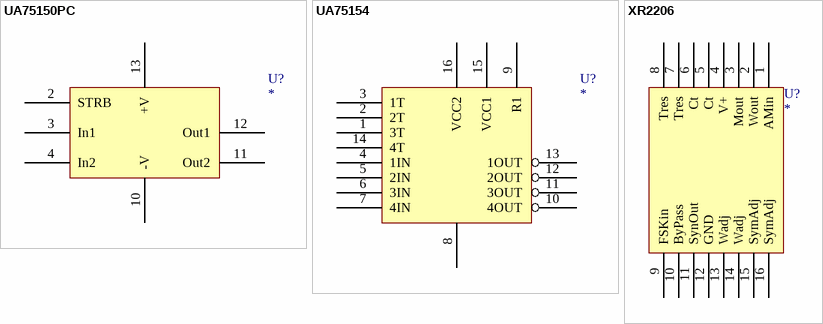
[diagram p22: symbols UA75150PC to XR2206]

## UA75150PC
designator U?
footprint DIP-14
pins: 2 STRB, 3 In1, 4 In2, 5 GND (power) hidden to GND, 10 -V, 11 Out2, 12 Out1, 13 +V
2 alternate drawings of the same symbol

## UA75154
designator U?
footprint DIP-16
pins: 1 3T, 2 2T, 3 1T, 4 1IN, 5 2IN, 6 3IN, 7 4IN, 8, 9 R1, 10 4OUT, 11 3OUT, 12 2OUT, 13 1OUT, 14 4T, 15 VCC1, 16 VCC2
2 alternate drawings of the same symbol

## XR2206
designator U?
footprint DIP-16
pins: 1 AMin, 2 Wout, 3 Mout, 4 V+, 5 Ct, 6 Ct, 7 Tres, 8 Tres, 9 FSKin, 10 ByPass, 11 SynOut, 12 GND, 13 Wadj, 14 Wadj, 15 SymAdj, 16 SymAdj
2 alternate drawings of the same symbol


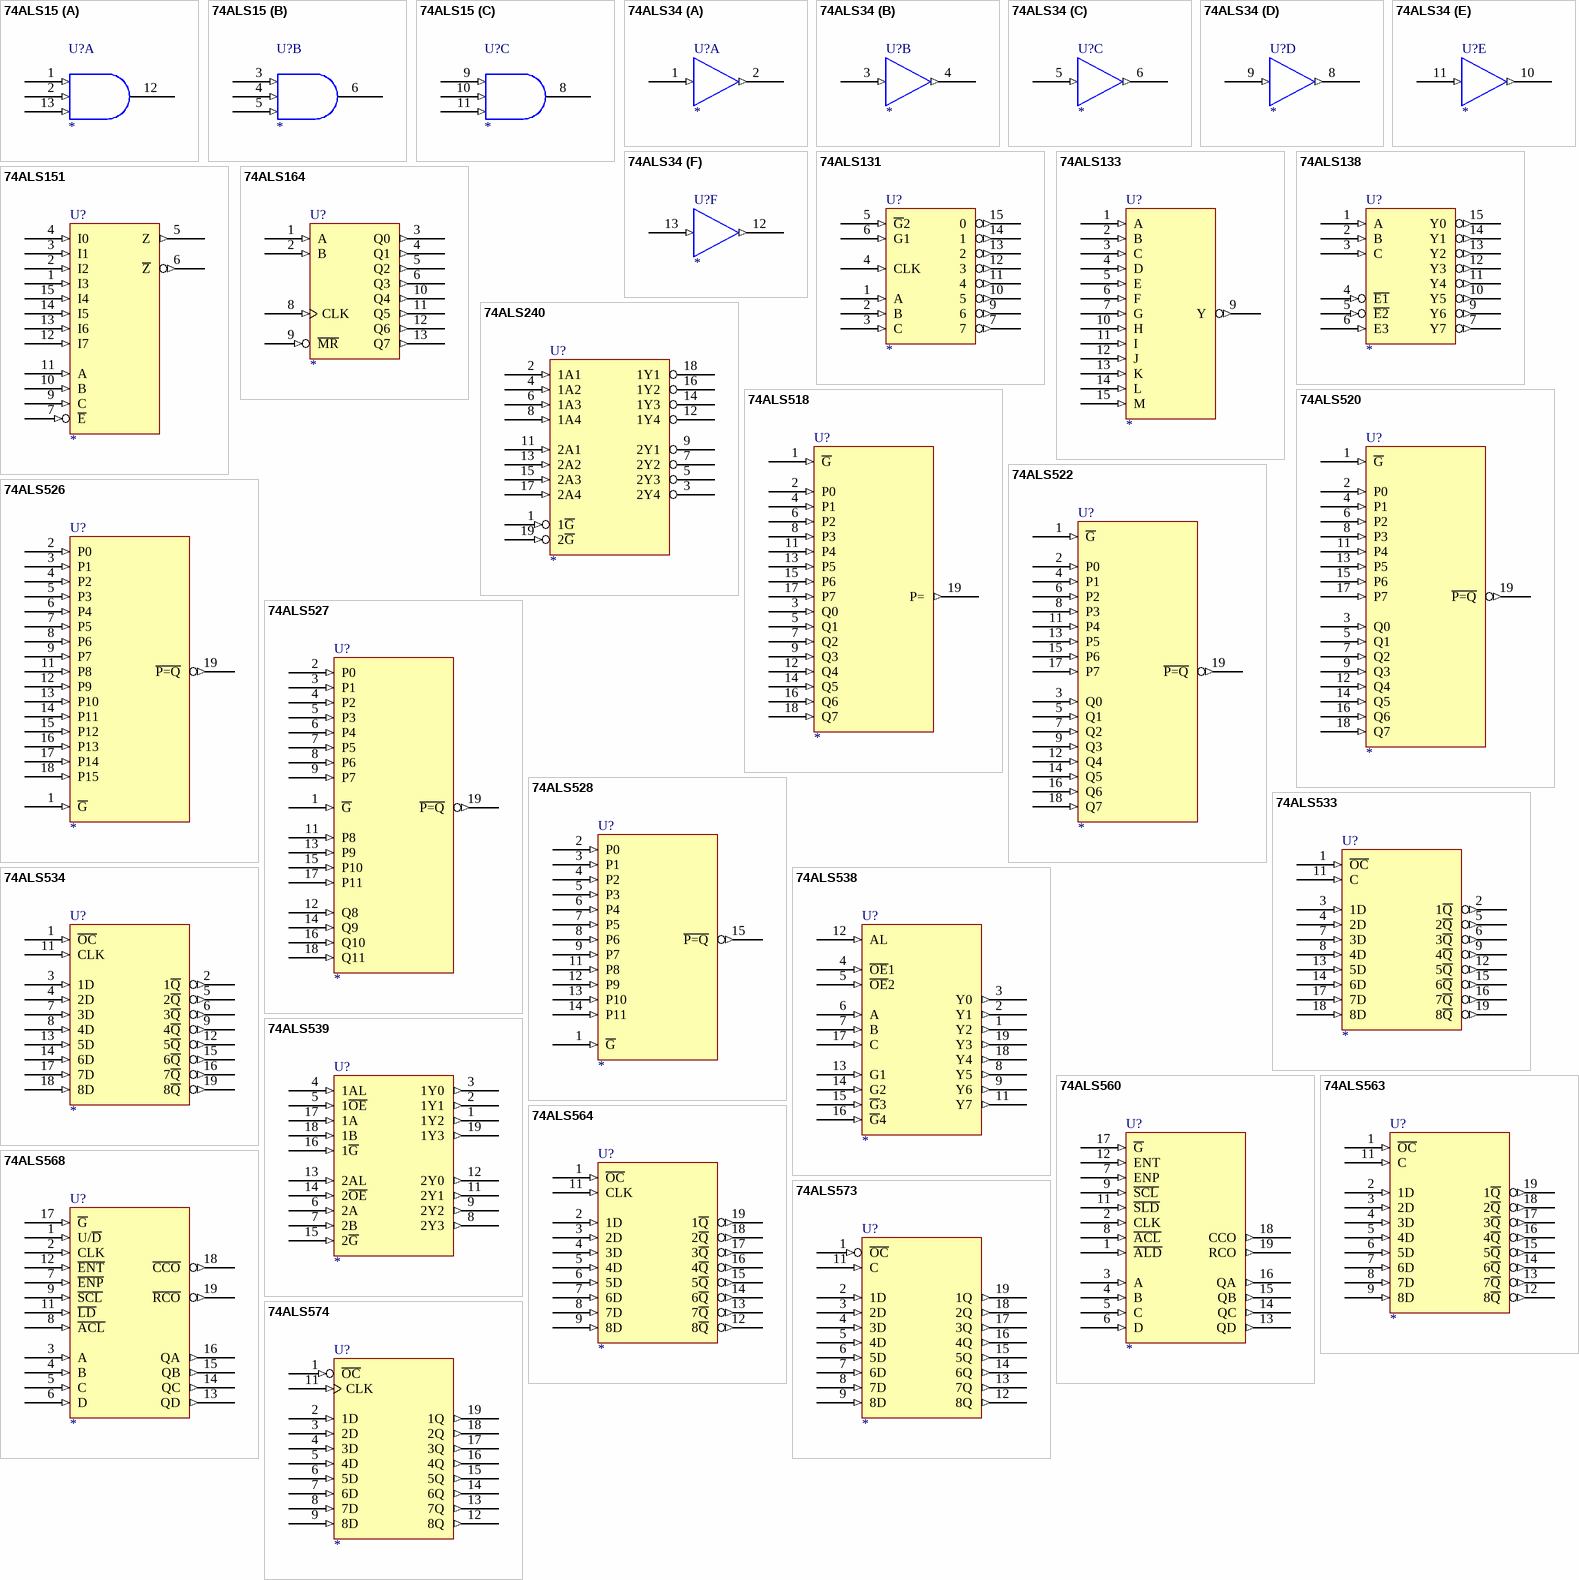
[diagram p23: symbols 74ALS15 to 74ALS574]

## 74ALS15
designator U?
footprint DIP-14
part A pins: 1 (in), 2 (in), 7 GND (power) hidden to GND, 12 (oc), 13 (in), 14 VCC (power) hidden to VCC
part B pins: 3 (in), 4 (in), 5 (in), 6 (oc), 7 GND (power) hidden to GND, 14 VCC (power) hidden to VCC
part C pins: 7 GND (power) hidden to GND, 8 (oc), 9 (in), 10 (in), 11 (in), 14 VCC (power) hidden to VCC
2 alternate drawings of the same symbol

## 74ALS34
designator U?
footprint DIP-14
part A pins: 1 (in), 2 (out), 7 GND (power) hidden to GND, 14 VCC (power) hidden to VCC
part B pins: 3 (in), 4 (out), 7 GND (power) hidden to GND, 14 VCC (power) hidden to VCC
part C pins: 5 (in), 6 (out), 7 GND (power) hidden to GND, 14 VCC (power) hidden to VCC
part D pins: 7 GND (power) hidden to GND, 8 (out), 9 (in), 14 VCC (power) hidden to VCC
part E pins: 7 GND (power) hidden to GND, 10 (out), 11 (in), 14 VCC (power) hidden to VCC
part F pins: 7 GND (power) hidden to GND, 12 (out), 13 (in), 14 VCC (power) hidden to VCC
2 alternate drawings of the same symbol

## 74ALS131
designator U?
footprint DIP-16
pins: 1 A (in), 2 B (in), 3 C (in), 4 CLK (in), 5 ~{G}2 (in), 6 G1 (in), 7 (out), 8 GND (power) hidden to GND, 9 6 (out), 10 5 (out), 11 4 (out), 12 3 (out), 13 2 (out), 14 1 (out), 15 0 (out), 16 VCC (power) hidden to VCC
2 alternate drawings of the same symbol

## 74ALS133
designator U?
footprint DIP-16
pins: 1 A (in), 2 B (in), 3 C (in), 4 D (in), 5 E (in), 6 F (in), 7 G (in), 8 GND (power) hidden to GND, 9 Y (out), 10 H (in), 11 I (in), 12 J (in), 13 K (in), 14 L (in), 15 M (in), 16 VCC (power) hidden to VCC
2 alternate drawings of the same symbol

## 74ALS138
designator U?
footprint DIP-16
pins: 1 A (in), 2 B (in), 3 C (in), 4 ~{E1} (in), 5 ~{E2} (in), 6 E3 (in), 7 Y7 (out), 8 GND (power) hidden to GND, 9 Y6 (out), 10 Y5 (out), 11 Y4 (out), 12 Y3 (out), 13 Y2 (out), 14 Y1 (out), 15 Y0 (out), 16 VCC (power) hidden to VCC
2 alternate drawings of the same symbol

## 74ALS151
designator U?
footprint DIP-16
pins: 1 I3 (in), 2 I2 (in), 3 I1 (in), 4 I0 (in), 5 Z (out), 6 ~{Z} (out), 7 ~{E} (in), 8 GND (power) hidden to GND, 9 C (in), 10 B (in), 11 A (in), 12 I7 (in), 13 I6 (in), 14 I5 (in), 15 I4 (in), 16 VCC (power) hidden to VCC
2 alternate drawings of the same symbol

## 74ALS164
designator U?
footprint DIP-14
pins: 1 A (in), 2 B (in), 3 Q0 (out), 4 Q1 (out), 5 Q2 (out), 6 Q3 (out), 7 GND (power) hidden to GND, 8 CLK (in), 9 ~{MR} (in), 10 Q4 (out), 11 Q5 (out), 12 Q6 (out), 13 Q7 (out), 14 VCC (power) hidden to VCC
2 alternate drawings of the same symbol

## 74ALS240
designator U?
footprint DIP-20
pins: 1 1~{G} (in), 2 1A1 (in), 3 2Y4 (hiz), 4 1A2 (in), 5 2Y3 (hiz), 6 1A3 (in), 7 2Y2 (hiz), 8 1A4 (in), 9 2Y1 (hiz), 10 GND (power) hidden to GND, 11 2A1 (in), 12 1Y4 (hiz), 13 2A2 (in), 14 1Y3 (hiz), 15 2A3 (in), 16 1Y2 (hiz), 17 2A4 (in), 18 1Y1 (hiz), 19 2~{G} (in), 20 VCC (power) hidden to VCC
2 alternate drawings of the same symbol

## 74ALS518
designator U?
footprint DIP-20
pins: 1 ~{G} (in), 2 P0 (in), 3 Q0 (in), 4 P1 (in), 5 Q1 (in), 6 P2 (in), 7 Q2 (in), 8 P3 (in), 9 Q3 (in), 10 GND (power) hidden to GND, 11 P4 (in), 12 Q4 (in), 13 P5 (in), 14 Q5 (in), 15 P6 (in), 16 Q6 (in), 17 P7 (in), 18 Q7 (in), 19 P= (out), 20 VCC (power) hidden to VCC
2 alternate drawings of the same symbol

## 74ALS520
designator U?
footprint DIP-20
pins: 1 ~{G} (in), 2 P0 (in), 3 Q0 (in), 4 P1 (in), 5 Q1 (in), 6 P2 (in), 7 Q2 (in), 8 P3 (in), 9 Q3 (in), 10 GND (power) hidden to GND, 11 P4 (in), 12 Q4 (in), 13 P5 (in), 14 Q5 (in), 15 P6 (in), 16 Q6 (in), 17 P7 (in), 18 Q7 (in), 19 ~{P=Q} (out), 20 VCC (power) hidden to VCC
2 alternate drawings of the same symbol

## 74ALS522
designator U?
footprint DIP-20
pins: 1 ~{G} (in), 2 P0 (in), 3 Q0 (in), 4 P1 (in), 5 Q1 (in), 6 P2 (in), 7 Q2 (in), 8 P3 (in), 9 Q3 (in), 10 GND (power) hidden to GND, 11 P4 (in), 12 Q4 (in), 13 P5 (in), 14 Q5 (in), 15 P6 (in), 16 Q6 (in), 17 P7 (in), 18 Q7 (in), 19 ~{P=Q} (out), 20 VCC (power) hidden to VCC
2 alternate drawings of the same symbol

## 74ALS526
designator U?
footprint DIP-20
pins: 1 ~{G} (in), 2 P0 (in), 3 P1 (in), 4 P2 (in), 5 P3 (in), 6 P4 (in), 7 P5 (in), 8 P6 (in), 9 P7 (in), 10 GND (power) hidden to GND, 11 P8 (in), 12 P9 (in), 13 P10 (in), 14 P11 (in), 15 P12 (in), 16 P13 (in), 17 P14 (in), 18 P15 (in), 19 ~{P=Q} (out), 20 VCC (power) hidden to VCC
2 alternate drawings of the same symbol

## 74ALS527
designator U?
footprint DIP-20
pins: 1 ~{G} (in), 2 P0 (in), 3 P1 (in), 4 P2 (in), 5 P3 (in), 6 P4 (in), 7 P5 (in), 8 P6 (in), 9 P7 (in), 10 GND (power) hidden to GND, 11 P8 (in), 12 Q8 (in), 13 P9 (in), 14 Q9 (in), 15 P10 (in), 16 Q10 (in), 17 P11 (in), 18 Q11 (in), 19 ~{P=Q} (out), 20 VCC (power) hidden to VCC
2 alternate drawings of the same symbol

## 74ALS528
designator U?
footprint DIP-16
pins: 1 ~{G} (in), 2 P0 (in), 3 P1 (in), 4 P2 (in), 5 P3 (in), 6 P4 (in), 7 P5 (in), 8 P6 (in), 8 GND (power) hidden to GND, 9 P7 (in), 11 P8 (in), 12 P9 (in), 13 P10 (in), 14 P11 (in), 15 ~{P=Q} (out), 16 VCC (power) hidden to VCC
2 alternate drawings of the same symbol

## 74ALS533
designator U?
footprint DIP-20
pins: 1 ~{OC} (in), 2 1~{Q} (out), 3 1D (in), 4 2D (in), 5 2~{Q} (out), 6 3~{Q} (out), 7 3D (in), 8 4D (in), 9 4~{Q} (out), 10 GND (power) hidden to GND, 11 C (in), 12 5~{Q} (out), 13 5D (in), 14 6D (in), 15 6~{Q} (out), 16 7~{Q} (out), 17 7D (in), 18 8D (in), 19 8~{Q} (out), 20 VCC (power) hidden to VCC
2 alternate drawings of the same symbol

## 74ALS534
designator U?
footprint DIP-20
pins: 1 ~{OC} (in), 2 1~{Q} (out), 3 1D (in), 4 2D (in), 5 2~{Q} (out), 6 3~{Q} (out), 7 3D (in), 8 4D (in), 9 4~{Q} (out), 10 GND (power) hidden to GND, 11 CLK (in), 12 5~{Q} (out), 13 5D (in), 14 6D (in), 15 6~{Q} (out), 16 7~{Q} (out), 17 7D (in), 18 8D (in), 19 8~{Q} (out), 20 VCC (power) hidden to VCC
2 alternate drawings of the same symbol

## 74ALS538
designator U?
footprint DIP-20
pins: 1 Y2 (out), 2 Y1 (out), 3 Y0 (out), 4 ~{OE}1 (in), 5 ~{OE}2 (in), 6 A (in), 7 B (in), 8 Y5 (out), 9 Y6 (out), 10 GND (power) hidden to GND, 11 Y7 (out), 12 AL (in), 13 G1 (in), 14 G2 (in), 15 ~{G}3 (in), 16 ~{G}4 (in), 17 C (in), 18 Y4 (out), 19 Y3 (out), 20 VCC (power) hidden to VCC
2 alternate drawings of the same symbol

## 74ALS539
designator U?
footprint DIP-20
pins: 1 1Y2 (out), 2 1Y1 (out), 3 1Y0 (out), 4 1AL (in), 5 1~{OE} (in), 6 2A (in), 7 2B (in), 8 2Y3 (out), 9 2Y2 (out), 10 GND (power) hidden to GND, 11 2Y1 (out), 12 2Y0 (out), 13 2AL (in), 14 2~{OE} (in), 15 2~{G} (in), 16 1~{G} (in), 17 1A (in), 18 1B (in), 19 1Y3 (out), 20 VCC (power) hidden to VCC
2 alternate drawings of the same symbol

## 74ALS560
designator U?
footprint DIP-20
pins: 1 ~{ALD} (in), 2 CLK (in), 3 A (in), 4 B (in), 5 C (in), 6 D (in), 7 ENP (in), 8 ~{ACL} (in), 9 ~{SCL} (in), 10 GND (power) hidden to GND, 11 ~{SLD} (in), 12 ENT (in), 13 QD (out), 14 QC (out), 15 QB (out), 16 QA (out), 17 ~{G} (in), 18 CCO (out), 19 RCO (out), 20 GND (power) hidden to GND
2 alternate drawings of the same symbol

## 74ALS563
designator U?
footprint DIP-20
pins: 1 ~{OC} (in), 2 1D (in), 3 2D (in), 4 3D (in), 5 4D (in), 6 5D (in), 7 6D (in), 8 7D (in), 9 8D (in), 10 GND (power) hidden to GND, 11 C (in), 12 8~{Q} (out), 13 7~{Q} (out), 14 6~{Q} (out), 15 5~{Q} (out), 16 4~{Q} (out), 17 3~{Q} (out), 18 2~{Q} (out), 19 1~{Q} (out), 20 VCC (power) hidden to VCC
2 alternate drawings of the same symbol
